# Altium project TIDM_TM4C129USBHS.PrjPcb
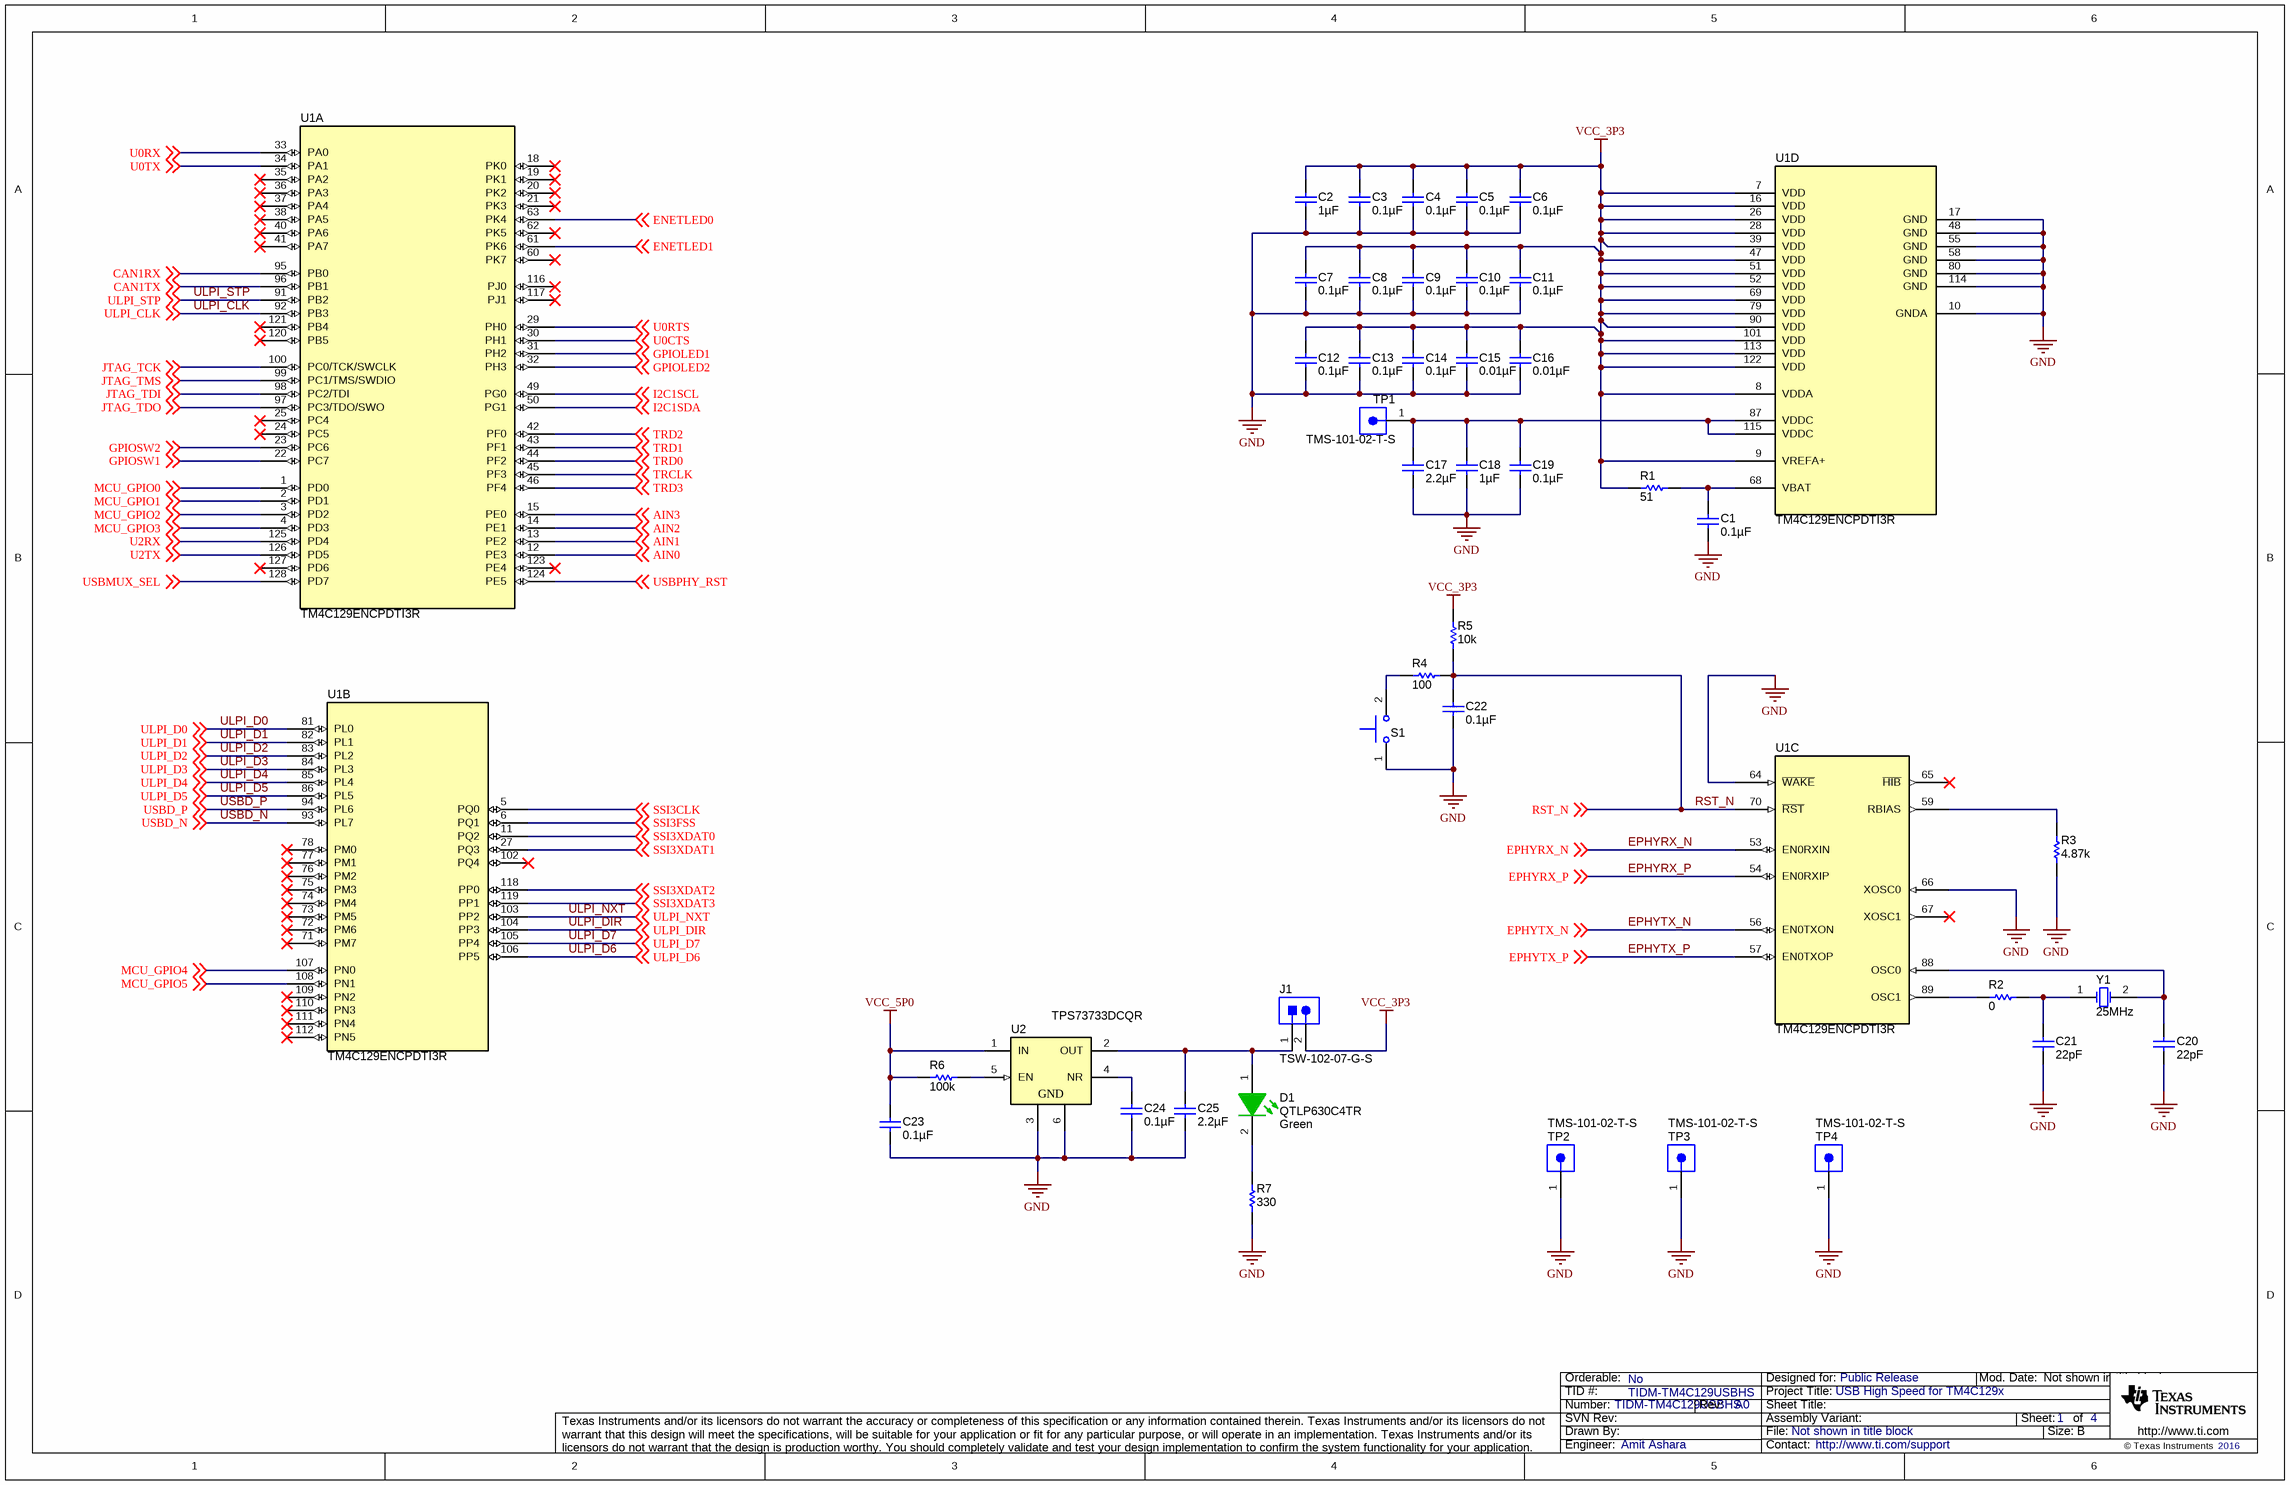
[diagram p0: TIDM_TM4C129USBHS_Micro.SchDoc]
TID: TIDM-TM4C129USBHS; TechSupport: http://www.ti.com/support; SCH_Rev: A0; PRJ_Title: USB High Speed for TM4C129x; PRJ_Number: TIDM-TM4C129USBHS; PRJ_Engineer: Amit Ashara; PRJ_Customer: Public Release; PCB_Rev: A0; PCB_Layout: Amit Ashara; EVM_Orderable: No; CopyrightYear: 2016
4 sheets, 137 parts. Net scope: global (net labels, ports and power ports of the same name join across sheets).
Board file: TIDM_TM4C129USBHS.PcbDoc
Sheets:
  TIDM_TM4C129USBHS_Micro.SchDoc
  TIDM_TM4C129USBHS_Connector.SchDoc
  TIDM_TM4C129USBHS_Ethernet.SchDoc
  TIDM_TM4C129USBHS_USB.SchDoc

## Sheet TIDM_TM4C129USBHS_Micro.SchDoc
size 431 x 279 mm; Date: Not shown in title block; ApprovedBy: Not shown in title block; CheckedBy: Not shown in title block; Author: Not shown in title block; CompanyName: Not shown in title block; Engineer: Not shown in title block; Organization: Not shown in title block; Address1: Not shown in title block; Address2: Not shown in title block; Address3: Not shown in title block; Address4: Not shown in title block; DocumentNumber: 1; Revision: Use project parameter SCH_Rev; SheetNumber: 1; SheetTotal: 4; PageSetup: Record=PageOptions¦CenterHorizontal=True¦CenterVertical=True¦PrintScale=1.00¦XCorrection=1.00¦YCorrection=1.00¦PrintKind=0¦BorderSize=5000000¦LeftOffset=0¦BottomOffset=0¦Orientation=2¦PaperLength=1000¦PaperWidth=1000¦Scale=100¦PaperSource=15¦PrintQuality=600¦MediaType=1¦DitherType=10¦PaperKind=Letter¦PrintScaleMode=1

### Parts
C1  ValueDisplayed: 0.1µF  [0402]  (hidden comment: GRM155R71C104KA88D)
C2  ValueDisplayed: 1µF  [0402]  (hidden comment: C1005X5R1C105K050BC)
C3  ValueDisplayed: 0.1µF  [0402]  (hidden comment: GRM155R71C104KA88D)
C4  ValueDisplayed: 0.1µF  [0402]  (hidden comment: GRM155R71C104KA88D)
C5  ValueDisplayed: 0.1µF  [0402]  (hidden comment: GRM155R71C104KA88D)
C6  ValueDisplayed: 0.1µF  [0402]  (hidden comment: GRM155R71C104KA88D)
C7  ValueDisplayed: 0.1µF  [0402]  (hidden comment: GRM155R71C104KA88D)
C8  ValueDisplayed: 0.1µF  [0402]  (hidden comment: GRM155R71C104KA88D)
C9  ValueDisplayed: 0.1µF  [0402]  (hidden comment: GRM155R71C104KA88D)
C10  ValueDisplayed: 0.1µF  [0402]  (hidden comment: GRM155R71C104KA88D)
C11  ValueDisplayed: 0.1µF  [0402]  (hidden comment: GRM155R71C104KA88D)
C12  ValueDisplayed: 0.1µF  [0402]  (hidden comment: GRM155R71C104KA88D)
C13  ValueDisplayed: 0.1µF  [0402]  (hidden comment: GRM155R71C104KA88D)
C14  ValueDisplayed: 0.1µF  [0402]  (hidden comment: GRM155R71C104KA88D)
C15  ValueDisplayed: 0.01µF  [0402]  (hidden comment: GRM155R71C103KA01D)
C16  ValueDisplayed: 0.01µF  [0402]  (hidden comment: GRM155R71C103KA01D)
C17  ValueDisplayed: 2.2µF  [0402]  (hidden comment: GRM155R61C225KE11D)
C18  ValueDisplayed: 1µF  [0402]  (hidden comment: C1005X5R1C105K050BC)
C19  ValueDisplayed: 0.1µF  [0402]  (hidden comment: GRM155R71C104KA88D)
C20  ValueDisplayed: 22pF  [0402]  (hidden comment: C1005C0G1H220J050BA)
C21  ValueDisplayed: 22pF  [0402]  (hidden comment: C1005C0G1H220J050BA)
C22  ValueDisplayed: 0.1µF  [0603]  (hidden comment: C0603C104J3RAC)
C23  ValueDisplayed: 0.1µF  [0603]  (hidden comment: EMK107B7104KA-T)
C24  ValueDisplayed: 0.1µF  [0603]  (hidden comment: EMK107B7104KA-T)
C25  ValueDisplayed: 2.2µF  [0603]  (hidden comment: GRM188R61C225KE15D)
D1  QTLP630C4TR  value Green  [QTLP630C_Green]
J1  TSW-102-07-G-S  [TSW-102-07-G-S]
R1  ValueDisplayed: 51  [0603]  (hidden comment: CRCW060351R0JNEA)
R2  ValueDisplayed: 0  [0402]  (hidden comment: ERJ-2GE0R00X)
R3  ValueDisplayed: 4.87k  [0402]  (hidden comment: CRCW04024K87FKED)
R4  ValueDisplayed: 100  [0402]  (hidden comment: CRCW0402100RJNED)
R5  ValueDisplayed: 10k  [0402]  (hidden comment: CRCW040210K0JNED)
R6  ValueDisplayed: 100k  [0402]  (hidden comment: ERJ-2RKF1003X)
R7  ValueDisplayed: 330  [0603]  (hidden comment: RC0603JR-07330RL)
S1  SKRKAEE010  [SW_SKRKAEE010]  (value not drawn)
TP1  TMS-101-02-T-S  [SAMTEC_TMS-101-02-T-S]
TP2  TMS-101-02-T-S  [SAMTEC_TMS-101-02-T-S]
TP3  TMS-101-02-T-S  [SAMTEC_TMS-101-02-T-S]
TP4  TMS-101-02-T-S  [SAMTEC_TMS-101-02-T-S]
U1  TM4C129ENCPDTI3R  [PDT0128A_N]  (parts A,B,C,D of 4)
U2  TPS73733DCQR  [DCQ0006A_N]
Y1  Frequency: 25MHz  [NDK_NX5032GA]  (hidden comment: NX5032GA-25.000M-STD-CSK-4)

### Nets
GND: C1.2 C2.2 C3.2 C4.2 C5.2 C6.2 C7.2 C8.2 C9.2 C10.2 C11.2 C12.2 C13.2 C14.2 C15.2 C16.2 C17.2 C18.2 C19.2 C20.2 C21.2 C22.2 C23.2 C24.2 C25.2 R3.1 R7.2 S1.1 TP2.1 TP3.1 TP4.1 U1.10(GNDA) U1.17(GND) U1.48(GND) U1.55(GND) U1.58(GND) U1.64(~{WAKE}) U1.66(XOSC0) U1.80(GND) U1.114(GND) U2.3(GND) U2.6(GND)
VCC_3P3: C2.1 C3.1 C4.1 C5.1 C6.1 C7.1 C8.1 C9.1 C10.1 C11.1 C12.1 C13.1 C14.1 C15.1 C16.1 J1.2 R1.1 R5.2 U1.7(VDD) U1.8(VDDA) U1.9(VREFA+) U1.16(VDD) U1.26(VDD) U1.28(VDD) U1.39(VDD) U1.47(VDD) U1.51(VDD) U1.52(VDD) U1.69(VDD) U1.79(VDD) U1.90(VDD) U1.101(VDD) U1.113(VDD) U1.122(VDD)
VCC_5P0: C23.1 R6.1 U2.1(IN)
AIN0: U1.12(PE3) ; off-sheet AIN0
AIN1: U1.13(PE2) ; off-sheet AIN1
AIN2: U1.14(PE1) ; off-sheet AIN2
AIN3: U1.15(PE0) ; off-sheet AIN3
CAN1RX: U1.95(PB0) ; off-sheet CAN1RX
CAN1TX: U1.96(PB1) ; off-sheet CAN1TX
ENETLED0: U1.63(PK4) ; off-sheet ENETLED0
ENETLED1: U1.61(PK6) ; off-sheet ENETLED1
EPHYRX_N: U1.53(EN0RXIN) ; off-sheet EPHYRX_N
EPHYRX_P: U1.54(EN0RXIP) ; off-sheet EPHYRX_P
EPHYTX_N: U1.56(EN0TXON) ; off-sheet EPHYTX_N
EPHYTX_P: U1.57(EN0TXOP) ; off-sheet EPHYTX_P
GPIOLED1: U1.31(PH2) ; off-sheet GPIOLED1
GPIOLED2: U1.32(PH3) ; off-sheet GPIOLED2
GPIOSW1: U1.22(PC7) ; off-sheet GPIOSW1
GPIOSW2: U1.23(PC6) ; off-sheet GPIOSW2
I2C1SCL: U1.49(PG0) ; off-sheet I2C1SCL
I2C1SDA: U1.50(PG1) ; off-sheet I2C1SDA
JTAG_TCK: U1.100(PC0/TCK/SWCLK) ; off-sheet JTAG_TCK
JTAG_TDI: U1.98(PC2/TDI) ; off-sheet JTAG_TDI
JTAG_TDO: U1.97(PC3/TDO/SWO) ; off-sheet JTAG_TDO
JTAG_TMS: U1.99(PC1/TMS/SWDIO) ; off-sheet JTAG_TMS
MCU_GPIO0: U1.1(PD0) ; off-sheet MCU_GPIO0
MCU_GPIO1: U1.2(PD1) ; off-sheet MCU_GPIO1
MCU_GPIO2: U1.3(PD2) ; off-sheet MCU_GPIO2
MCU_GPIO3: U1.4(PD3) ; off-sheet MCU_GPIO3
MCU_GPIO4: U1.107(PN0) ; off-sheet MCU_GPIO4
MCU_GPIO5: U1.108(PN1) ; off-sheet MCU_GPIO5
RST_N: C22.1 R4.1 R5.1 U1.70(~{RST}) ; off-sheet RST_N
SSI3CLK: U1.5(PQ0) ; off-sheet SSI3CLK
SSI3FSS: U1.6(PQ1) ; off-sheet SSI3FSS
SSI3XDAT0: U1.11(PQ2) ; off-sheet SSI3XDAT0
SSI3XDAT1: U1.27(PQ3) ; off-sheet SSI3XDAT1
SSI3XDAT2: U1.118(PP0) ; off-sheet SSI3XDAT2
SSI3XDAT3: U1.119(PP1) ; off-sheet SSI3XDAT3
TRCLK: U1.45(PF3) ; off-sheet TRCLK
TRD0: U1.44(PF2) ; off-sheet TRD0
TRD1: U1.43(PF1) ; off-sheet TRD1
TRD2: U1.42(PF0) ; off-sheet TRD2
TRD3: U1.46(PF4) ; off-sheet TRD3
U0CTS: U1.30(PH1) ; off-sheet U0CTS
U0RTS: U1.29(PH0) ; off-sheet U0RTS
U0RX: U1.33(PA0) ; off-sheet U0RX
U0TX: U1.34(PA1) ; off-sheet U0TX
U2RX: U1.125(PD4) ; off-sheet U2RX
U2TX: U1.126(PD5) ; off-sheet U2TX
ULPI_CLK: U1.92(PB3) ; off-sheet ULPI_CLK
ULPI_D0: U1.81(PL0) ; off-sheet ULPI_D0
ULPI_D1: U1.82(PL1) ; off-sheet ULPI_D1
ULPI_D2: U1.83(PL2) ; off-sheet ULPI_D2
ULPI_D3: U1.84(PL3) ; off-sheet ULPI_D3
ULPI_D4: U1.85(PL4) ; off-sheet ULPI_D4
ULPI_D5: U1.86(PL5) ; off-sheet ULPI_D5
ULPI_D6: U1.106(PP5) ; off-sheet ULPI_D6
ULPI_D7: U1.105(PP4) ; off-sheet ULPI_D7
ULPI_DIR: U1.104(PP3) ; off-sheet ULPI_DIR
ULPI_NXT: U1.103(PP2) ; off-sheet ULPI_NXT
ULPI_STP: U1.91(PB2) ; off-sheet ULPI_STP
USBD_N: U1.93(PL7) ; off-sheet USBD_N
USBD_P: U1.94(PL6) ; off-sheet USBD_P
USBMUX_SEL: U1.128(PD7) ; off-sheet USBMUX_SEL
USBPHY_RST: U1.124(PE5) ; off-sheet USBPHY_RST
NetC1_1: C1.1 R1.2 U1.68(VBAT)
NetC17_1: C17.1 C18.1 C19.1 TP1.1 U1.87(VDDC) U1.115(VDDC)
NetC20_1: C20.1 U1.88(OSC0) Y1.2(OSC2)
NetC21_1: C21.1 R2.2 Y1.1(OSC1)
NetC24_1: C24.1 U2.4(NR)
NetC25_1: C25.1 D1.1(A) J1.1 U2.2(OUT)
NetD1_2: D1.2(K) R7.1
NetR2_1: R2.1 U1.89(OSC1)
NetR3_2: R3.2 U1.59(RBIAS)
NetR4_2: R4.2 S1.2
NetR6_2: R6.2 U2.5(EN)

Not connected (* = marked no-connect by the designer): U1 18(PK0)* 19(PK1)* 20(PK2)* 21(PK3)* 24(PC5)* 25(PC4)* 35(PA2)* 36(PA3)* 37(PA4)* 38(PA5)* 40(PA6)* 41(PA7)* 60(PK7)* 62(PK5)* 65(~{HIB})* 67(XOSC1)* 71(PM7)* 72(PM6)* 73(PM5)* 74(PM4)* 75(PM3)* 76(PM2)* 77(PM1)* 78(PM0)* 102(PQ4)* 109(PN2)* 110(PN3)* 111(PN4)* 112(PN5)* 116(PJ0)* 117(PJ1)* 120(PB5)* 121(PB4)* 123(PE4)* 127(PD6)*

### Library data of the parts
C1 C3-C14 C19 = GRM155R71C104KA88D: CAP, CERM, 0.1 µF, 16 V, +/- 10%, X7R, 0402; Manufacturer: MuRata; Polarized: N; CompType: Capacitor; Value: 0.1uF; U/M: EA; Cap_F: 0.0000001; Tolerance_%: 10; Value1: Unknown; VDC_V: 16; Value2: 16V; TaMin_C: -55; TaMax_C: 125; AEC Category: Q200
C2 C18 = C1005X5R1C105K050BC: CAP, CERM, 1 µF, 16 V, +/- 10%, X5R, 0402; Manufacturer: TDK; Polarized: N; CompType: Capacitor; Value: 1uF; U/M: EA; Cap_F: 0.000001; Tolerance_%: 10; Value1: Unknown; VDC_V: 16; Value2: 16V; TaMin_C: -55; TaMax_C: 85; AEC Category: Q200
C15 C16 = GRM155R71C103KA01D: CAP, CERM, 0.01 µF, 16 V, +/- 10%, X7R, 0402; Manufacturer: MuRata; Polarized: N; CompType: Capacitor; Value: 0.01uF; U/M: EA; Cap_F: 0.00000001; Tolerance_%: 10; Value1: Unknown; VDC_V: 16; Value2: 16V; TaMin_C: -55; TaMax_C: 125; AEC Category: Q200
C17 = GRM155R61C225KE11D: CAP, CERM, 2.2 µF, 16 V, +/- 10%, X5R, 0402; Manufacturer: MuRata; Polarized: N; CompType: Capacitor; Value: 2.2uF; U/M: EA; Cap_F: 0.0000022; Tolerance_%: 10; Value1: Unknown; VDC_V: 16; Value2: 16V; TaMin_C: -55; TaMax_C: 85; AEC Category: Q200
C20 C21 = C1005C0G1H220J050BA: CAP, CERM, 22 pF, 50 V, +/- 5%, C0G/NP0, 0402; Manufacturer: TDK; Polarized: N; CompType: Capacitor; Value: 22pF; U/M: EA; Cap_F: 0.000000000022; Tolerance_%: 5; Value1: Unknown; VDC_V: 50; Value2: 50V; TaMin_C: -55; TaMax_C: 125; AEC Category: Q200
C22 = C0603C104J3RAC: CAP, CERM, 0.1 µF, 25 V, +/- 5%, X7R, 0603; Manufacturer: Kemet; Polarized: N; CompType: Capacitor; Value: 0.1uF; U/M: EA; Cap_F: 0.0000001; Tolerance_%: 5; Value1: Unknown; VDC_V: 25; Value2: 25V; TaMin_C: -55; TaMax_C: 125; AEC Category: Q200
C23 C24 = EMK107B7104KA-T: CAP, CERM, 0.1 µF, 16 V, +/- 10%, X7R, 0603; Manufacturer: Taiyo Yuden; Polarized: N; CompType: Capacitor; Value: 0.1uF; U/M: EA; Cap_F: 0.0000001; Tolerance_%: 10; Value1: Unknown; VDC_V: 16; Value2: 16V; TaMin_C: -55; TaMax_C: 125; AEC Category: Q200
C25 = GRM188R61C225KE15D: CAP, CERM, 2.2 µF, 16 V, +/- 10%, X5R, 0603; Manufacturer: MuRata; Polarized: N; CompType: Capacitor; Value: 2.2uF; U/M: EA; Cap_F: 0.0000022; Tolerance_%: 10; Value1: Unknown; VDC_V: 16; Value2: 16V; TaMin_C: -55; TaMax_C: 85; AEC Category: Q200
D1 = QTLP630C4TR: LED, Green, SMD; Manufacturer: Everlight; SymbolCreator: Altium; Vf_V: 2.1; Value2: 2.1V; Io_A: 0.02; Vr_V: 5; Tjmax_C: 85; Value1: W; Angle: 140; U/M: EA
J1 = TSW-102-07-G-S: Header, 100mil, 2x1, Gold, TH; Manufacturer: Samtec; SymbolCreator: a0412235; Pitch_mm: 2.54; Gender: Male; Shrouded: N; Row_Count: 1; Current_A: 6.3; Voltage_V: 550; Cert_CSA: Y
R1 = CRCW060351R0JNEA: RES, 51, 5%, 0.1 W, 0603; Manufacturer: Vishay-Dale; CompType: Resistor; Value: 51; Value_Code: 51R0; Tolerance_%: 5; Power_W: 0.1; Value2: 0.1W; VDC_V: 75; TempCo: 200 ppm/C; EIA_Code: E24; U/M: EA; AEC Category: Q200
R2 = ERJ-2GE0R00X: RES, 0, 5%, 0.063 W, 0402; Manufacturer: Panasonic; CompType: Resistor; Value: 0; Value_Code: 0000; Tolerance_%: 5; Power_W: 0.063; Value2: 0.063W; VDC_V: 50; TempCo: 600 ppm/C; EIA_Code: E24; U/M: EA; AEC Category: Q200
R3 = CRCW04024K87FKED: RES, 4.87 k, 1%, 0.063 W, 0402; Manufacturer: Vishay-Dale; CompType: Resistor; Value: 4.87k; Res_ohm: 4870; Value_Code: 4k87; Tolerance_%: 1; Power_W: 0.063; Value2: 0.063W; VDC_V: 50; TempCo: 100 ppm/C; EIA_Code: E96; U/M: EA; AEC Category: Q200
R4 = CRCW0402100RJNED: RES, 100, 5%, 0.063 W, 0402; Manufacturer: Vishay-Dale; CompType: Resistor; Value: 100; Value_Code: 100R; Tolerance_%: 5; Power_W: 0.063; Value2: 0.063W; VDC_V: 50; TempCo: 200 ppm/C; EIA_Code: E24; U/M: EA; AEC Category: Q200
R5 = CRCW040210K0JNED: RES, 10 k, 5%, 0.063 W, 0402; Manufacturer: Vishay-Dale; CompType: Resistor; Value: 10k; Res_ohm: 10000; Value_Code: 10k0; Tolerance_%: 5; Power_W: 0.063; Value2: 0.063W; VDC_V: 50; TempCo: 200 ppm/C; EIA_Code: E24; U/M: EA; AEC Category: Q200
R6 = ERJ-2RKF1003X: RES, 100 k, 1%, 0.1 W, 0402; Manufacturer: Panasonic; CompType: Resistor; Value: 100k; Res_ohm: 100000; Tolerance_%: 1; Power_W: 0.1; Value2: 0.1W; VDC_V: 50; TempCo: 100 ppm/C; EIA_Code: E96; U/M: EA; AEC Category: Q200
R7 = RC0603JR-07330RL: RES, 330, 5%, 0.1 W, 0603; Manufacturer: Yageo America; CompType: Resistor; Value: 330; Value_Code: 330R; Tolerance_%: 5; Power_W: 0.1; Value2: 0.1W; VDC_V: 50; TempCo: 100 ppm/C; EIA_Code: E24; U/M: EA; AEC Category: Q200
S1 = SKRKAEE010: Switch, Push Button, SMD; Manufacturer: Alps; SymbolCreator: a0412235; Circuit: SPST-NO; VDC_V: 12; SwitchFunction: Off-Mom; PositionCount: 1; CurrentRating_mA: 50
TP1-TP4 = TMS-101-02-T-S: Header, 1x1, Tin, TH; Manufacturer: Samtec; SymbolCreator: a0412235
U1 = TM4C129ENCPDTI3R: Tiva C Series Microcontroller, PDT0128A; Manufacturer: Texas Instruments; SymbolCreator: a0411947; CompType: IC; U/M: EA
U2 = TPS73733DCQR: Single Output LDO, 1 A, Fixed 3.3 V Output, 2.2 to 5.5 V Input, with Reverse Current Protection, 6-pin SOT-223 (DCQ), -40 to 125 degC, Green (RoHS & no Sb/Br); Manufacturer: Texas Instruments; Alternate PartNumber: Equivalent; Accuracy(%): 3; Fixed Output Options(V): 3.3; Iout(Max)(A): 1; Iq(Typ)(mA): 0.3; Rating: Catalog; SubFamily: Single Channel LDO; Vdo(Typ)(mV): 130; Vin(Max)(V): 5.5; Vin(Min)(V): 2.2
Y1 = NX5032GA-25.000M-STD-CSK-4: Crystal, 25MHz,  SMD; Manufacturer: NDK; SymbolCreator: a0412235; U/M: EA; TaMin_C: -40; TaMax_C: 150; Frequency Stability: ±30ppm

## Sheet TIDM_TM4C129USBHS_Connector.SchDoc
size 431 x 279 mm; Date: Not shown in title block; ApprovedBy: Not shown in title block; CheckedBy: Not shown in title block; Author: Not shown in title block; CompanyName: Not shown in title block; Engineer: Not shown in title block; Organization: Not shown in title block; Address1: Not shown in title block; Address2: Not shown in title block; Address3: Not shown in title block; Address4: Not shown in title block; DocumentNumber: 1; Revision: Use project parameter SCH_Rev; SheetNumber: 2; SheetTotal: 4; PageSetup: Record=PageOptions¦CenterHorizontal=True¦CenterVertical=True¦PrintScale=1.00¦XCorrection=1.00¦YCorrection=1.00¦PrintKind=0¦BorderSize=5000000¦LeftOffset=0¦BottomOffset=0¦Orientation=2¦PaperLength=1000¦PaperWidth=1000¦Scale=100¦PaperSource=15¦PrintQuality=600¦MediaType=1¦DitherType=10¦PaperKind=Letter¦PrintScaleMode=1
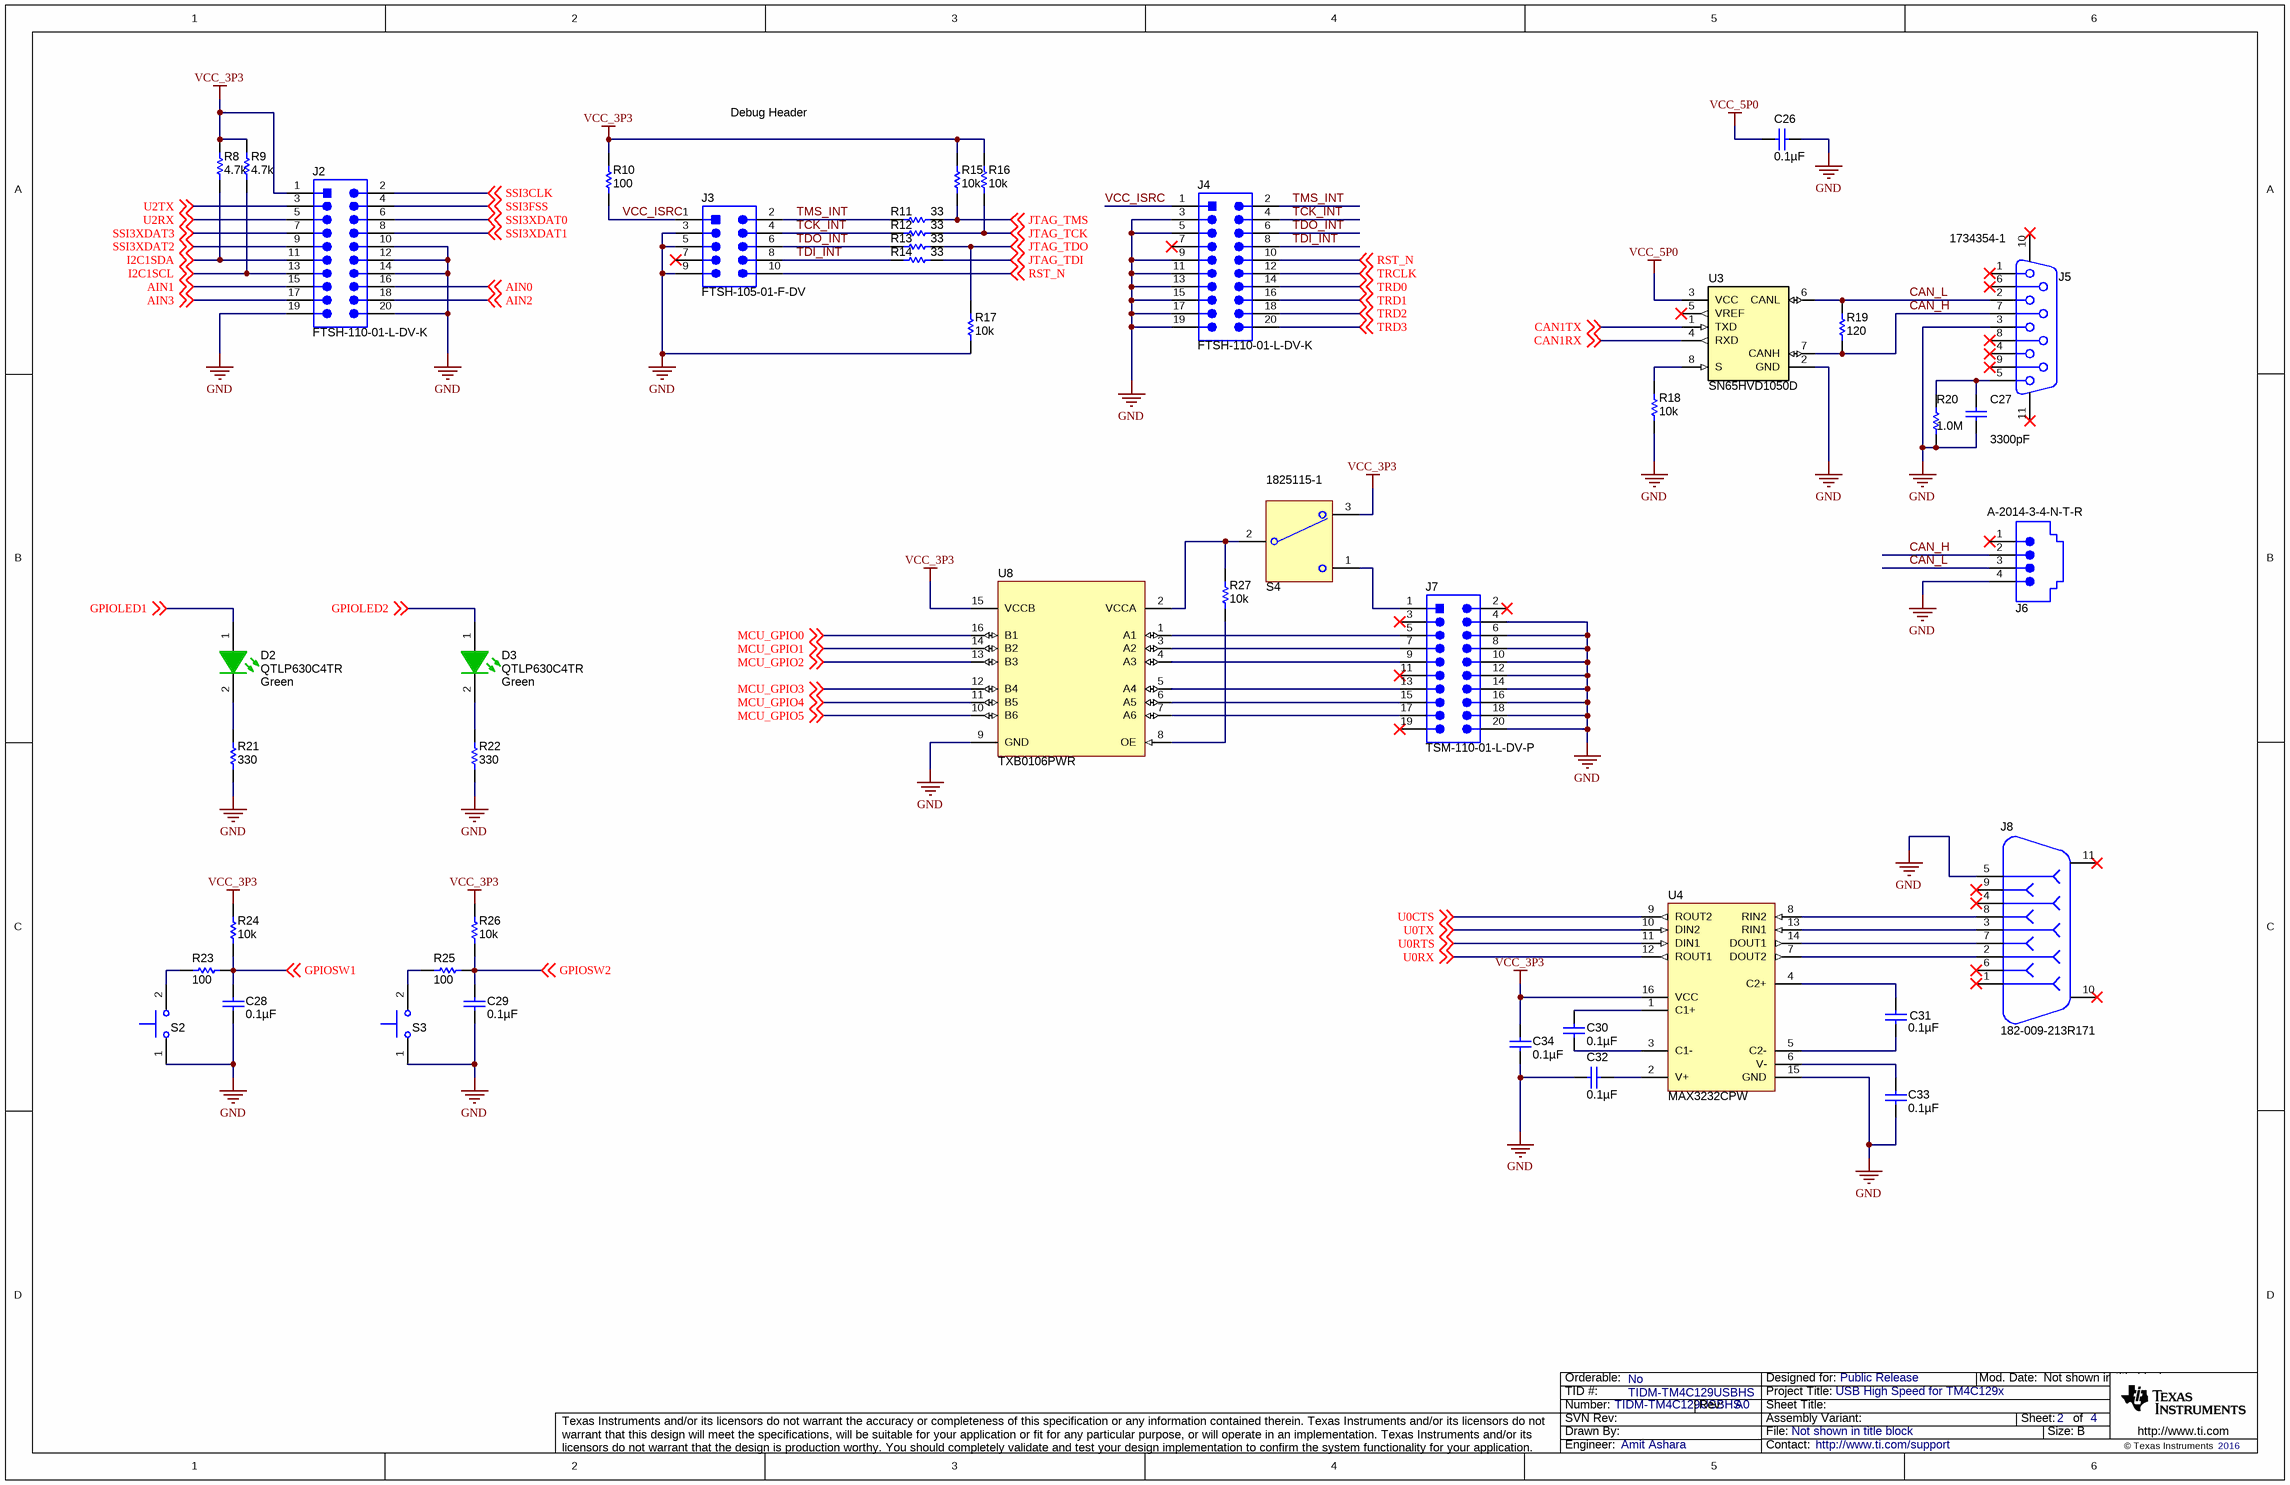
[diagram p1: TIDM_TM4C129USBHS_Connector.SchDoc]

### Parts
C26  ValueDisplayed: 0.1µF  [0402]  (hidden comment: GRM155R71C104KA88D)
C27  ValueDisplayed: 3300pF  [0603]  (hidden comment: C0603X332K5RACTU)
C28  ValueDisplayed: 0.1µF  [0603]  (hidden comment: C0603C104J3RAC)
C29  ValueDisplayed: 0.1µF  [0603]  (hidden comment: C0603C104J3RAC)
C30  ValueDisplayed: 0.1µF  [0402]  (hidden comment: C1005X5R0J104K)
C31  ValueDisplayed: 0.1µF  [0402]  (hidden comment: C1005X5R0J104K)
C32  ValueDisplayed: 0.1µF  [0805_HV]  (hidden comment: 08053C104KAT2A)
C33  ValueDisplayed: 0.1µF  [0402]  (hidden comment: C1005X5R0J104K)
C34  ValueDisplayed: 0.1µF  [0402]  (hidden comment: C1005X5R0J104K)
D2  QTLP630C4TR  value Green  [QTLP630C_Green]
D3  QTLP630C4TR  value Green  [QTLP630C_Green]
J2  FTSH-110-01-L-DV-K  [Samtec_FTSH-110-01-x-DV-K]
J3  FTSH-105-01-F-DV  [Samtec_FTSH-105-01-x-DV]
J4  FTSH-110-01-L-DV-K  [Samtec_FTSH-110-01-x-DV-K]
J5  1734354-1  [TE_1734354-1]
J6  A-2014-3-4-N-T-R  [Assman_A-2014-3-x-N-T-R]
J7  TSM-110-01-L-DV-P  [CONN_TSM-110-01-T-DV-P]
J8  182-009-213R171  [NORCOMP_182-009-213R171]
R8  ValueDisplayed: 4.7k  [0603]  (hidden comment: CRCW06034K70JNEA)
R9  ValueDisplayed: 4.7k  [0603]  (hidden comment: CRCW06034K70JNEA)
R10  ValueDisplayed: 100  [0603]  (hidden comment: CRCW0603100RJNEA)
R11  ValueDisplayed: 33  [0603]  (hidden comment: CRCW060333R0JNEA)
R12  ValueDisplayed: 33  [0603]  (hidden comment: CRCW060333R0JNEA)
R13  ValueDisplayed: 33  [0603]  (hidden comment: CRCW060333R0JNEA)
R14  ValueDisplayed: 33  [0603]  (hidden comment: CRCW060333R0JNEA)
R15  ValueDisplayed: 10k  [0603]  (hidden comment: CRCW060310K0JNEA)
R16  ValueDisplayed: 10k  [0603]  (hidden comment: CRCW060310K0JNEA)
R17  ValueDisplayed: 10k  [0603]  (hidden comment: CRCW060310K0JNEA)
R18  ValueDisplayed: 10k  [0603]  (hidden comment: CRCW060310K0JNEA)
R19  ValueDisplayed: 120  [0603]  (hidden comment: RC0603FR-07120RL)
R20  ValueDisplayed: 1.0M  [0603]  (hidden comment: CRCW06031M00JNEA)
R21  ValueDisplayed: 330  [0603]  (hidden comment: RC0603JR-07330RL)
R22  ValueDisplayed: 330  [0603]  (hidden comment: RC0603JR-07330RL)
R23  ValueDisplayed: 100  [0402]  (hidden comment: CRCW0402100RJNED)
R24  ValueDisplayed: 10k  [0402]  (hidden comment: CRCW040210K0JNED)
R25  ValueDisplayed: 100  [0402]  (hidden comment: CRCW0402100RJNED)
R26  ValueDisplayed: 10k  [0402]  (hidden comment: CRCW040210K0JNED)
R27  ValueDisplayed: 10k  [0603]  (hidden comment: CRCW060310K0JNEA)
S2  SKRKAEE010  [SW_SKRKAEE010]  (value not drawn)
S3  SKRKAEE010  [SW_SKRKAEE010]  (value not drawn)
S4  1825115-1  [SW_1825115-1]
U3  SN65HVD1050D  [D0008A_L]
U4  MAX3232CPW  [PW0016A_N]
U8  TXB0106PWR  [PW0016A_N]

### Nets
GND: C26.2 C27.2 C28.2 C29.2 C32.1 C33.2 C34.2 J2.10 J2.12 J2.14 J2.19 J2.20 J3.3 J3.5 J3.9 J4.3 J4.5 J4.9 J4.11 J4.13 J4.15 J4.17 J4.19 J5.3 J6.4 J7.4 J7.6 J7.8 J7.10 J7.12 J7.14 J7.16 J7.18 J7.20 J8.5 R17.1 R18.1 R20.1 R21.2 R22.2 S2.1 S3.1 U3.2(GND) U4.15(GND) U8.9(GND)
VCC_3P3: C34.1 J2.1 R8.2 R9.2 R10.1 R15.2 R16.2 R24.2 R26.2 S4.3 U4.16(VCC) U8.15(VCCB)
VCC_5P0: C26.1 U3.3(VCC)
AIN0: J2.16 ; off-sheet AIN0
AIN1: J2.15 ; off-sheet AIN1
AIN2: J2.18 ; off-sheet AIN2
AIN3: J2.17 ; off-sheet AIN3
CAN1RX: U3.4(RXD) ; off-sheet CAN1RX
CAN1TX: U3.1(TXD) ; off-sheet CAN1TX
CAN_H: J5.7 J6.2 R19.1 U3.7(CANH)
CAN_L: J5.2 J6.3 R19.2 U3.6(CANL)
GPIOLED1: D2.1(A) ; off-sheet GPIOLED1
GPIOLED2: D3.1(A) ; off-sheet GPIOLED2
GPIOSW1: C28.1 R23.1 R24.1 ; off-sheet GPIOSW1
GPIOSW2: C29.1 R25.1 R26.1 ; off-sheet GPIOSW2
I2C1SCL: J2.13 R9.1 ; off-sheet I2C1SCL
I2C1SDA: J2.11 R8.1 ; off-sheet I2C1SDA
JTAG_TCK: R12.2 R16.1 ; off-sheet JTAG_TCK
JTAG_TDI: R14.2 ; off-sheet JTAG_TDI
JTAG_TDO: R13.2 R17.2 ; off-sheet JTAG_TDO
JTAG_TMS: R11.2 R15.1 ; off-sheet JTAG_TMS
MCU_GPIO0: U8.16(B1) ; off-sheet MCU_GPIO0
MCU_GPIO1: U8.14(B2) ; off-sheet MCU_GPIO1
MCU_GPIO2: U8.13(B3) ; off-sheet MCU_GPIO2
MCU_GPIO3: U8.12(B4) ; off-sheet MCU_GPIO3
MCU_GPIO4: U8.11(B5) ; off-sheet MCU_GPIO4
MCU_GPIO5: U8.10(B6) ; off-sheet MCU_GPIO5
RST_N: J3.10 J4.10 ; off-sheet RST_N
SSI3CLK: J2.2 ; off-sheet SSI3CLK
SSI3FSS: J2.4 ; off-sheet SSI3FSS
SSI3XDAT0: J2.6 ; off-sheet SSI3XDAT0
SSI3XDAT1: J2.8 ; off-sheet SSI3XDAT1
SSI3XDAT2: J2.9 ; off-sheet SSI3XDAT2
SSI3XDAT3: J2.7 ; off-sheet SSI3XDAT3
TCK_INT: J3.4 J4.4 R12.1
TDI_INT: J3.8 J4.8 R14.1
TDO_INT: J3.6 J4.6 R13.1
TMS_INT: J3.2 J4.2 R11.1
TRCLK: J4.12 ; off-sheet TRCLK
TRD0: J4.14 ; off-sheet TRD0
TRD1: J4.16 ; off-sheet TRD1
TRD2: J4.18 ; off-sheet TRD2
TRD3: J4.20 ; off-sheet TRD3
U0CTS: U4.9(ROUT2) ; off-sheet U0CTS
U0RTS: U4.11(DIN1) ; off-sheet U0RTS
U0RX: U4.12(ROUT1) ; off-sheet U0RX
U0TX: U4.10(DIN2) ; off-sheet U0TX
U2RX: J2.5 ; off-sheet U2RX
U2TX: J2.3 ; off-sheet U2TX
VCC_ISRC: J3.1 J4.1 R10.2
NetC27_1: C27.1 J5.5 R20.2
NetC30_1: C30.1 U4.1(C1+)
NetC30_2: C30.2 U4.3(C1-)
NetC31_1: C31.1 U4.4(C2+)
NetC31_2: C31.2 U4.5(C2-)
NetC32_2: C32.2 U4.2(V+)
NetC33_1: C33.1 U4.6(V-)
NetD2_2: D2.2(K) R21.1
NetD3_2: D3.2(K) R22.1
NetJ7_1: J7.1 S4.1
NetJ7_5: J7.5 U8.1(A1)
NetJ7_7: J7.7 U8.3(A2)
NetJ7_9: J7.9 U8.4(A3)
NetJ7_13: J7.13 U8.5(A4)
NetJ7_15: J7.15 U8.6(A5)
NetJ7_17: J7.17 U8.7(A6)
NetJ8_2: J8.2 U4.7(DOUT2)
NetJ8_3: J8.3 U4.13(RIN1)
NetJ8_7: J8.7 U4.14(DOUT1)
NetJ8_8: J8.8 U4.8(RIN2)
NetR18_2: R18.2 U3.8(S)
NetR23_2: R23.2 S2.2
NetR25_2: R25.2 S3.2
NetR27_1: R27.1 U8.8(OE)
NetR27_2: R27.2 S4.2(COM) U8.2(VCCA)

Not connected (* = marked no-connect by the designer): J3 7*; J4 7*; J5 1* 4* 6* 8* 9* 10* 11*; J6 1*; J7 2* 3* 11* 19*; J8 1* 4* 6* 9* 10* 11*; U3 5(VREF)*

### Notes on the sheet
- Debug Header

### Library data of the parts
C26 = GRM155R71C104KA88D: as C1 on sheet TIDM_TM4C129USBHS_Micro
C27 = C0603X332K5RACTU: CAP, CERM, 3300 pF, 50 V, +/- 10%, X7R, 0603; Manufacturer: Kemet; Polarized: N; CompType: Capacitor; Value: 3300pF; U/M: EA; Cap_F: 0.0000000033; Tolerance_%: 10; Value1: Unknown; VDC_V: 50; Value2: 50V; TaMin_C: -55; TaMax_C: 125; AEC Category: Q200
C28 C29 = C0603C104J3RAC: as C22 on sheet TIDM_TM4C129USBHS_Micro
C30 C31 C33 C34 = C1005X5R0J104K: CAP, CERM, 0.1 µF, 6.3 V, +/- 10%, X5R, 0402; Manufacturer: TDK; Polarized: N; CompType: Capacitor; Value: 0.1uF; U/M: EA; Cap_F: 0.0000001; Tolerance_%: 10; ESR_ohm: 0.0186; Value1: 0.0186 ohm; VDC_V: 6.3; Value2: 6.3V; TaMin_C: -55; TaMax_C: 85
C32 = 08053C104KAT2A: CAP, CERM, 0.1 µF, 25 V, +/- 10%, X7R, 0805; Manufacturer: AVX; Polarized: N; CompType: Capacitor; Value: 0.1uF; U/M: EA; Cap_F: 0.0000001; Tolerance_%: 10; ESR_ohm: 0.28; Value1: 0.28 ohm; VDC_V: 25; Value2: 25V; TaMin_C: -55; TaMax_C: 125; Cap_Case: 0805
D2 D3 = QTLP630C4TR: as D1 on sheet TIDM_TM4C129USBHS_Micro
J2 J4 = FTSH-110-01-L-DV-K: Header (Shrouded), 1.27mm, 10x2, Tin, SMT; Manufacturer: Samtec; SymbolCreator: a0412235; Pitch_mm: 1.27; Gender: Male; Shrouded: Y; Row_Count: 2; Current_A: 3.3
J3 = FTSH-105-01-F-DV: Header, 1.27mm, 5x2, Gold, Black, SMT; Manufacturer: Samtec; SymbolCreator: a0412235; Pitch_mm: 1.27; Gender: Male; Row_Count: 2; Current_A: 3.3; Cert_CSA: Y
J5 = 1734354-1: Receptacle, D-Sub, 9 Position, R/A, TH; Manufacturer: TE Connectivity; SymbolCreator: Altium; Gender: Female; ContactFinish: Gold
J6 = A-2014-3-4-N-T-R: Modular Connector, Jack, 4P4C, Gold, TH; Manufacturer: Assman WSW; SymbolCreator: Altium; Pitch_mm: 1.27; Gender: Female; Row_Count: 2; RowSpacing_mm: 2.54; Current_A: 1.5; Voltage_V: 125; Cert_UL: Y
J7 = TSM-110-01-L-DV-P: Header, 2.54mm, 10x2, Gold, SMT; Manufacturer: Samtec; SymbolCreator: a0412235; Pitch_mm: 2.54; Gender: Male; Shrouded: N; Row_Count: 2; Current_A: 5.4; Voltage_V: 475; Cert_CSA: Y
J8 = 182-009-213R171: CONN DB9 FEMALE R/A SOLDER TH; Manufacturer: NorComp; SymbolCreator: a0412235; CompType: Connector; U/M: EA
R8 R9 = CRCW06034K70JNEA: RES, 4.7 k, 5%, 0.1 W, 0603; Manufacturer: Vishay-Dale; CompType: Resistor; Value: 4.7k; Res_ohm: 4700; Value_Code: 4k70; Tolerance_%: 5; Power_W: 0.1; Value2: 0.1W; VDC_V: 75; TempCo: 200 ppm/C; EIA_Code: E24; U/M: EA; AEC Category: Q200
R10 = CRCW0603100RJNEA: RES, 100, 5%, 0.1 W, 0603; Manufacturer: Vishay-Dale; CompType: Resistor; Value: 100; Value_Code: 100R; Tolerance_%: 5; Power_W: 0.1; Value2: 0.1W; VDC_V: 75; TempCo: 200 ppm/C; EIA_Code: E24; U/M: EA; AEC Category: Q200
R11-R14 = CRCW060333R0JNEA: RES, 33, 5%, 0.1 W, 0603; Manufacturer: Vishay-Dale; CompType: Resistor; Value: 33; Value_Code: 33R0; Tolerance_%: 5; Power_W: 0.1; Value2: 0.1W; VDC_V: 75; TempCo: 200 ppm/C; EIA_Code: E24; U/M: EA; AEC Category: Q200
R15-R18 R27 = CRCW060310K0JNEA: RES, 10 k, 5%, 0.1 W, 0603; Manufacturer: Vishay-Dale; CompType: Resistor; Value: 10k; Res_ohm: 10000; Value_Code: 10k0; Tolerance_%: 5; Power_W: 0.1; Value2: 0.1W; VDC_V: 75; TempCo: 200 ppm/C; EIA_Code: E24; U/M: EA; AEC Category: Q200
R19 = RC0603FR-07120RL: RES, 120, 1%, 0.1 W, 0603; Manufacturer: Yageo America; CompType: Resistor; Value: 120; Value_Code: 120R; Tolerance_%: 1; Power_W: 0.1; Value2: 0.1W; VDC_V: 150; TempCo: 200 ppm/C; U/M: EA; AEC Category: Q200
R20 = CRCW06031M00JNEA: RES, 1.0 M, 5%, 0.1 W, 0603; Manufacturer: Vishay-Dale; CompType: Resistor; Value: 1.0Meg; Res_ohm: 1000000; Value_Code: 1M00; Tolerance_%: 5; Power_W: 0.1; Value2: 0.1W; VDC_V: 75; TempCo: 200 ppm/C; EIA_Code: E24; U/M: EA; AEC Category: Q200
R21 R22 = RC0603JR-07330RL: as R7 on sheet TIDM_TM4C129USBHS_Micro
R23 R25 = CRCW0402100RJNED: as R4 on sheet TIDM_TM4C129USBHS_Micro
R24 R26 = CRCW040210K0JNED: as R5 on sheet TIDM_TM4C129USBHS_Micro
S2 S3 = SKRKAEE010: as S1 on sheet TIDM_TM4C129USBHS_Micro
S4 = 1825115-1: Switch, SPDT, On-On, 2 Pos, TH; Manufacturer: TE Connectivity; SymbolCreator: x0208326; VDC_V: 12; PositionCount: 2; CurrentRating_mA: 150
U3 = SN65HVD1050D: High-Speed EMC Optimized CAN Transceiver, 70 mA, 5 V, -40 to 125 degC, 8-pin SOIC (D), Green (RoHS & no Sb/Br); Manufacturer: Texas Instruments; Alternate PartNumber: Equivalent; Drivers Per Package: 1; Bus Fault Voltage(V): -4 to 16; Transient Pulse Protection(V): -200 to 200; ICC(Max)(mA): 70; Supply Voltage(s)(V): 5; Rating: Catalog
U4 = MAX3232CPW: 3-V to 5.5-V Multichannel RS-232 Line Driver / Receiver with ±15-kV ESD Protection, 0 to 70 degC, 16-Pin TSSOP (PW), Green (RoHS & no Sb/Br); Manufacturer: Texas Instruments; Alternate Manufacturer: None; Alternate PartNumber: Equivalent; Drivers Per Package: 2; Supply Voltage(s)(V): 3.3 or 5.0; ESD HBM(kV): +/-15; ICC(Max)(mA): 1; Single Supply: TRUE
U8 = TXB0106PWR: 6-BIT BIDIRECTIONAL VOLTAGE-LEVEL TRANSLATOR WITH AUTO-DIRECTION SENSING AND ±15-kV ESD PROTECTION, PW0016A; Manufacturer: Texas Instruments; SymbolCreator: Altium; CompType: IC; U/M: EA

## Sheet TIDM_TM4C129USBHS_Ethernet.SchDoc
size 431 x 279 mm; Date: Not shown in title block; ApprovedBy: Not shown in title block; CheckedBy: Not shown in title block; Author: Not shown in title block; CompanyName: Not shown in title block; Engineer: Not shown in title block; Organization: Not shown in title block; Address1: Not shown in title block; Address2: Not shown in title block; Address3: Not shown in title block; Address4: Not shown in title block; DocumentNumber: 1; Revision: Use project parameter SCH_Rev; SheetNumber: 3; SheetTotal: 4; PageSetup: Record=PageOptions¦CenterHorizontal=True¦CenterVertical=True¦PrintScale=1.00¦XCorrection=1.00¦YCorrection=1.00¦PrintKind=0¦BorderSize=5000000¦LeftOffset=0¦BottomOffset=0¦Orientation=2¦PaperLength=1000¦PaperWidth=1000¦Scale=100¦PaperSource=15¦PrintQuality=600¦MediaType=1¦DitherType=10¦PaperKind=Letter¦PrintScaleMode=1
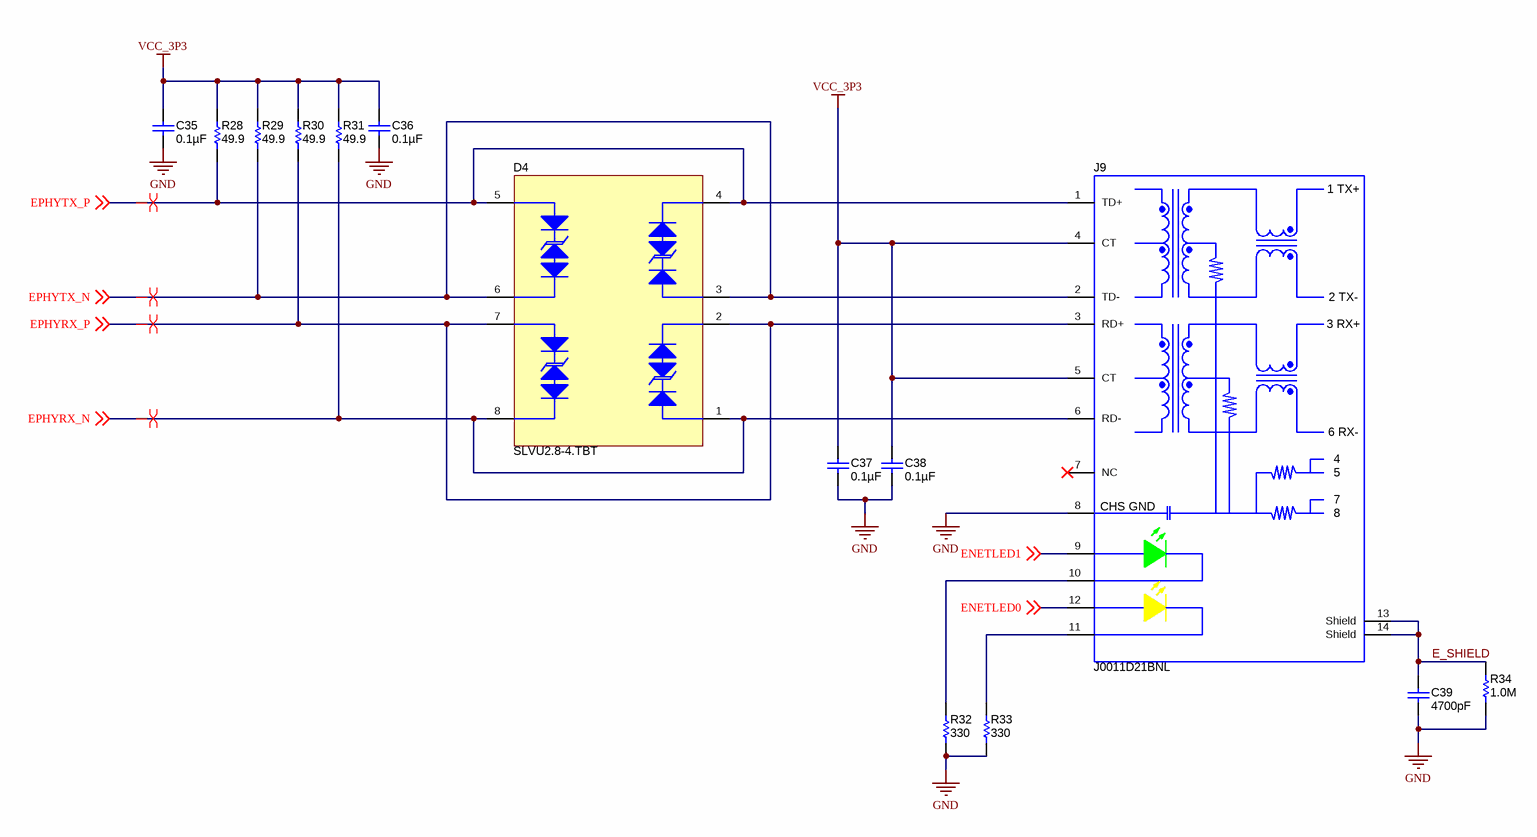
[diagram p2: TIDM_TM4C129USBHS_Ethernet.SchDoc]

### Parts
C35  ValueDisplayed: 0.1µF  [0402]  (hidden comment: GCM155R71C104KA55D)
C36  ValueDisplayed: 0.1µF  [0402]  (hidden comment: GCM155R71C104KA55D)
C37  ValueDisplayed: 0.1µF  [0402]  (hidden comment: GCM155R71C104KA55D)
C38  ValueDisplayed: 0.1µF  [0402]  (hidden comment: GCM155R71C104KA55D)
C39  ValueDisplayed: 4700pF  [1812]  (hidden comment: 1812GC472KA1)
D4  SLVU2.8-4.TBT  [SO-8]
J9  J0011D21BNL  [Pulse_J0011D21BNL]
R28  ValueDisplayed: 49.9  [0402]  (hidden comment: CRCW040249R9FKED)
R29  ValueDisplayed: 49.9  [0402]  (hidden comment: CRCW040249R9FKED)
R30  ValueDisplayed: 49.9  [0402]  (hidden comment: CRCW040249R9FKED)
R31  ValueDisplayed: 49.9  [0402]  (hidden comment: CRCW040249R9FKED)
R32  ValueDisplayed: 330  [0603]  (hidden comment: RC0603JR-07330RL)
R33  ValueDisplayed: 330  [0603]  (hidden comment: RC0603JR-07330RL)
R34  ValueDisplayed: 1.0M  [1206]  (hidden comment: CRCW12061M00JNEA)

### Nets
GND: C35.2 C36.2 C37.2 C38.2 C39.2 J9.8(CHS_GND) R32.2 R33.2 R34.1
VCC_3P3: C35.1 C36.1 C37.1 C38.1 J9.4(CT) J9.5(CT) R28.2 R29.2 R30.2 R31.2
E_SHIELD: C39.1 J9.13(Shield) J9.14(Shield) R34.2
ENETLED0: J9.12(RIGHT_LED) ; off-sheet ENETLED0
ENETLED1: J9.9(LEFT_LED_ANODE) ; off-sheet ENETLED1
EPHYRX_N: D4.1 D4.8 J9.6(RD-) R31.1 ; off-sheet EPHYRX_N
EPHYRX_P: D4.2 D4.7 J9.3(RD+) R30.1 ; off-sheet EPHYRX_P
EPHYTX_N: D4.3 D4.6 J9.2(TD-) R29.1 ; off-sheet EPHYTX_N
EPHYTX_P: D4.4 D4.5 J9.1(TD+) R28.1 ; off-sheet EPHYTX_P
NetJ9_10: J9.10(LEFT_LED) R32.1
NetJ9_11: J9.11(RIGHT_LED_ANODE) R33.1

Not connected (* = marked no-connect by the designer): J9 7(NC)*

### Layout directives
differential pair: EPHYRX_N, EPHYRX_P, EPHYTX_N, EPHYTX_P

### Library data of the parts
C35-C38 = GCM155R71C104KA55D: CAP, CERM, 0.1 µF, 16 V, +/- 10%, X7R, 0402; Manufacturer: MuRata; Polarized: N; CompType: Capacitor; Value: 0.1uF; U/M: EA; Cap_F: 0.0000001; Tolerance_%: 10; Value1: Unknown; VDC_V: 16; Value2: 16V; TaMin_C: -55; TaMax_C: 125; AEC Category: Q200
C39 = 1812GC472KA1: CAP, CERM, 4700 pF, 2000 V, +/- 10%, X7R, 1812; Manufacturer: AVX; Polarized: N; CompType: Capacitor; Value: 4700pF; U/M: EA; Cap_F: 0.0000000047; Tolerance_%: 10; Value1: Unknown; VDC_V: 2000; Value2: 2000V; TaMin_C: -55; TaMax_C: 125; AEC Category: Q200
D4 = SLVU2.8-4.TBT: Diode, TVS, Uni, 2.8 V, 400 W, SO-8; Manufacturer: Semtech; SymbolCreator: Altium; U/M: EA; Power_W: 400; Vr_V: 2.8; Value1: 400W; AEC Category: Q101
J9 = J0011D21BNL: Connector, RJ-45 with integrated magnetics, 1x1, Gold, R/A, TH; Manufacturer: Pulse Engineering; SymbolCreator: Altium
R28-R31 = CRCW040249R9FKED: RES, 49.9, 1%, 0.063 W, 0402; Manufacturer: Vishay-Dale; CompType: Resistor; Value: 49.9; Value_Code: 49R9; Tolerance_%: 1; Power_W: 0.063; Value2: 0.063W; VDC_V: 50; TempCo: 100 ppm/C; EIA_Code: E96; U/M: EA; AEC Category: Q200
R32 R33 = RC0603JR-07330RL: as R7 on sheet TIDM_TM4C129USBHS_Micro
R34 = CRCW12061M00JNEA: RES, 1.0 M, 5%, 0.25 W, 1206; Manufacturer: Vishay-Dale; CompType: Resistor; Value: 1.0Meg; Res_ohm: 1000000; Value_Code: 1M00; Tolerance_%: 5; Power_W: 0.25; Value2: 0.25W; VDC_V: 200; TempCo: 200 ppm/C; EIA_Code: E24; U/M: EA; AEC Category: Q200

## Sheet TIDM_TM4C129USBHS_USB.SchDoc
size 431 x 279 mm; Date: Not shown in title block; ApprovedBy: Not shown in title block; CheckedBy: Not shown in title block; Author: Not shown in title block; CompanyName: Not shown in title block; Engineer: Not shown in title block; Organization: Not shown in title block; Address1: Not shown in title block; Address2: Not shown in title block; Address3: Not shown in title block; Address4: Not shown in title block; DocumentNumber: 1; Revision: Use project parameter SCH_Rev; SheetNumber: 4; SheetTotal: 4; PageSetup: Record=PageOptions¦CenterHorizontal=True¦CenterVertical=True¦PrintScale=1.00¦XCorrection=1.00¦YCorrection=1.00¦PrintKind=0¦BorderSize=5000000¦LeftOffset=0¦BottomOffset=0¦Orientation=2¦PaperLength=1000¦PaperWidth=1000¦Scale=100¦PaperSource=15¦PrintQuality=600¦MediaType=1¦DitherType=10¦PaperKind=Letter¦PrintScaleMode=1
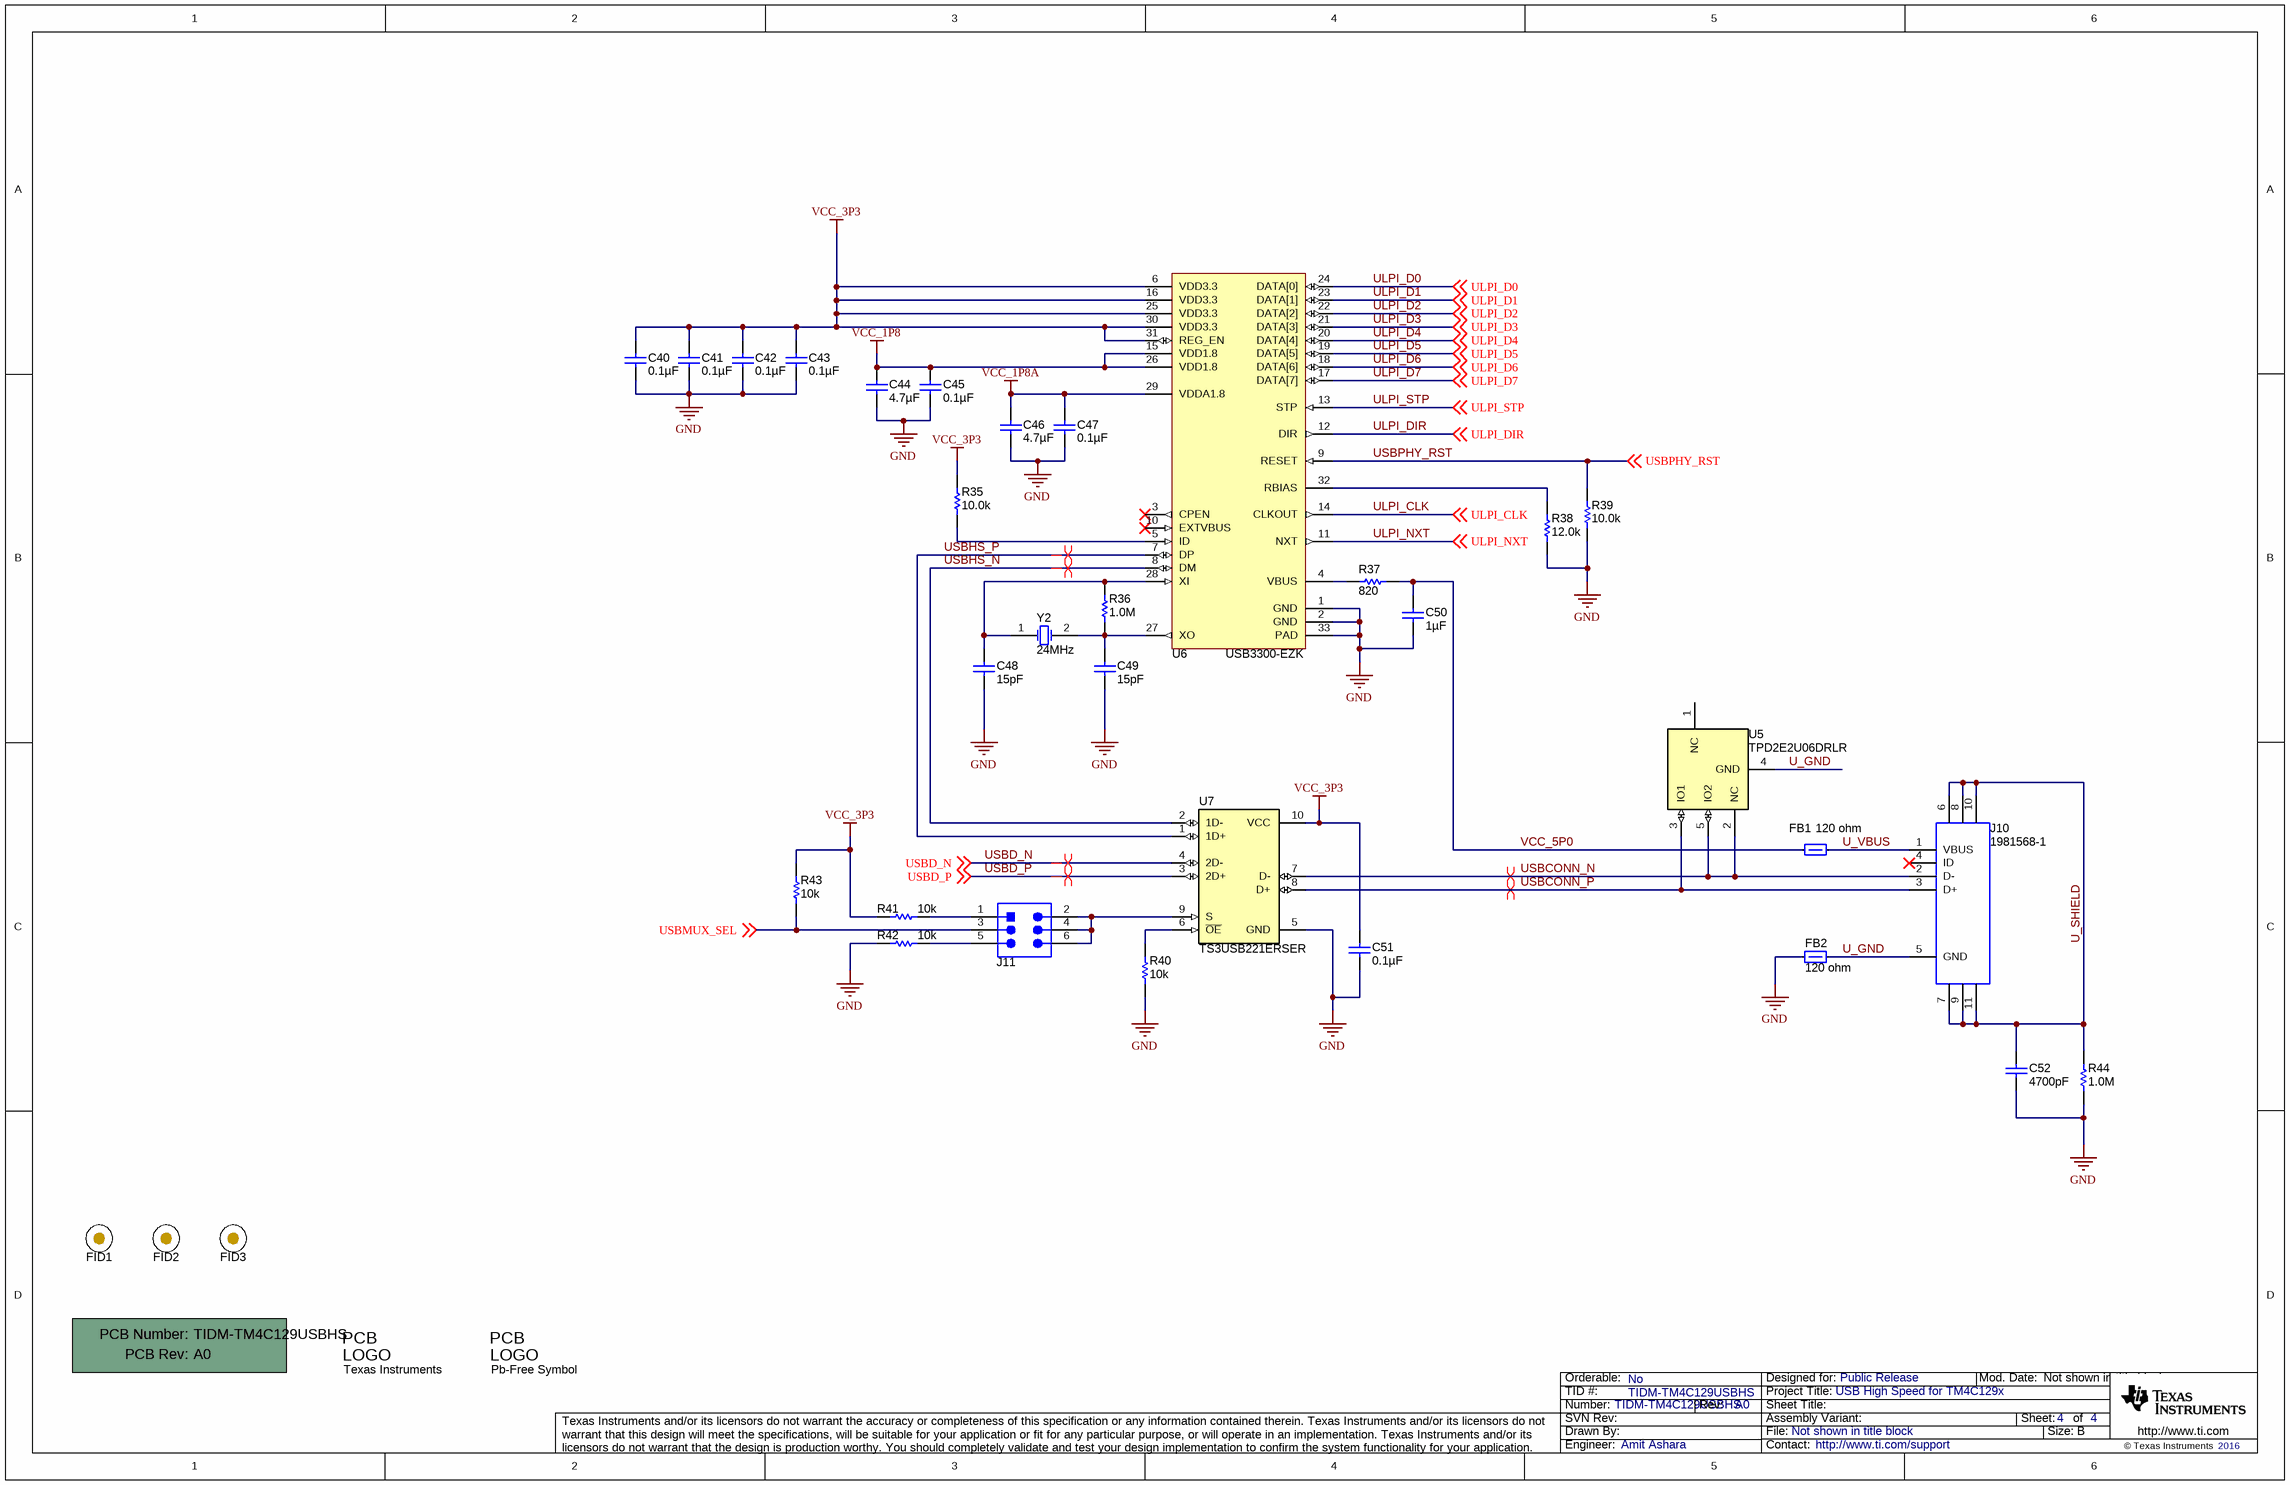
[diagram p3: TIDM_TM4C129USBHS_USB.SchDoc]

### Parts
!PCB  Printed Circuit Board  (value not drawn)  (mechanical)
C40  ValueDisplayed: 0.1µF  [0603]  (hidden comment: 06035C104KAT2A)
C41  ValueDisplayed: 0.1µF  [0603]  (hidden comment: 06035C104KAT2A)
C42  ValueDisplayed: 0.1µF  [0603]  (hidden comment: 06035C104KAT2A)
C43  ValueDisplayed: 0.1µF  [0603]  (hidden comment: 06035C104KAT2A)
C44  ValueDisplayed: 4.7µF  [0805_HV]  (hidden comment: C2012X7R1A475M)
C45  ValueDisplayed: 0.1µF  [0603]  (hidden comment: 06035C104KAT2A)
C46  ValueDisplayed: 4.7µF  [0805_HV]  (hidden comment: C2012X7R1A475M)
C47  ValueDisplayed: 0.1µF  [0603]  (hidden comment: 06035C104KAT2A)
C48  ValueDisplayed: 15pF  [0603]  (hidden comment: 06035A150JAT2A)
C49  ValueDisplayed: 15pF  [0603]  (hidden comment: 06035A150JAT2A)
C50  ValueDisplayed: 1µF  [0603]  (hidden comment: GRM188R71A105KA61D)
C51  ValueDisplayed: 0.1µF  [0603]  (hidden comment: 06035C104KAT2A)
C52  ValueDisplayed: 4700pF  [1812]  (hidden comment: 1812GC472KA1)
FB1  value 120 ohm  [0603]  (hidden comment: BLM18AG121SN1D)
FB2  value 120 ohm  [0603]  (hidden comment: BLM18AG121SN1D)
FID1  Fiducial  [Fiducial10-20]  (value not drawn)
FID2  Fiducial  [Fiducial10-20]  (value not drawn)
FID3  Fiducial  [Fiducial10-20]  (value not drawn)
J10  1981568-1  [TE_1981568-1]
J11  TSW-103-07-G-D  [TSW-103-07-G-D]  (value not drawn)
Logo1  Texas Instruments  [TI_Stacked_Overlay_Small]  (no BOM)
Logo2  Pb-Free Symbol  [Pb-Free_Overlay_Small]  (no BOM)
R35  ValueDisplayed: 10.0k  [0603]  (hidden comment: RCG060310K0FKEA)
R36  ValueDisplayed: 1.0M  [0603]  (hidden comment: CRCW06031M00JNEA)
R37  ValueDisplayed: 820  [0603]  (hidden comment: RC0603FR-07820RL)
R38  ValueDisplayed: 12.0k  [0603]  (hidden comment: RC0603FR-0712KL)
R39  ValueDisplayed: 10.0k  [0603]  (hidden comment: RCG060310K0FKEA)
R40  ValueDisplayed: 10k  [0603]  (hidden comment: RC0603JR-0710KL)
R41  ValueDisplayed: 10k  [0603]  (hidden comment: RC0603JR-0710KL)
R42  ValueDisplayed: 10k  [0603]  (hidden comment: RC0603JR-0710KL)
R43  ValueDisplayed: 10k  [0603]  (hidden comment: RC0603JR-0710KL)
R44  ValueDisplayed: 1.0M  [1206]  (hidden comment: CRCW12061M00JNEA)
U5  TPD2E2U06DRLR  [DRL0005A]
U6  USB3300-EZK  [Microchip_32QFN-3304-5x5B]
U7  TS3USB221ERSER  [RSE0010A]
Y2  Frequency: 24MHz  [NDK_NX5032GA]  (hidden comment: NX5032GA-24.000M-STD-CSK-4)

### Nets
GND: C40.2 C41.2 C42.2 C43.2 C44.2 C45.2 C46.2 C47.2 C48.2 C49.2 C50.2 C51.1 C52.2 FB2.2 R38.1 R39.1 R40.1 R42.2 R44.1 U6.1(GND) U6.2(GND) U6.33(PAD) U7.5(GND)
VCC_1P8: C44.1 C45.1 U6.15(VDD1.8) U6.26(VDD1.8)
VCC_1P8A: C46.1 C47.1 U6.29(VDDA1.8)
VCC_3P3: C40.1 C41.1 C42.1 C43.1 C51.2 R35.2 R41.2 R43.2 U6.6(VDD3.3) U6.16(VDD3.3) U6.25(VDD3.3) U6.30(VDD3.3) U6.31(REG_EN) U7.10(VCC)
VCC_5P0: C50.1 FB1.1 R37.2
U_GND: FB2.1 J10.5(GND) U5.4(GND)
U_SHIELD: C52.1 J10.6 J10.7 J10.8 J10.9 J10.10 J10.11 R44.2
U_VBUS: FB1.2 J10.1(VBUS)
ULPI_CLK: U6.14(CLKOUT) ; off-sheet ULPI_CLK
ULPI_D0: U6.24(DATA[0]) ; off-sheet ULPI_D0
ULPI_D1: U6.23(DATA[1]) ; off-sheet ULPI_D1
ULPI_D2: U6.22(DATA[2]) ; off-sheet ULPI_D2
ULPI_D3: U6.21(DATA[3]) ; off-sheet ULPI_D3
ULPI_D4: U6.20(DATA[4]) ; off-sheet ULPI_D4
ULPI_D5: U6.19(DATA[5]) ; off-sheet ULPI_D5
ULPI_D6: U6.18(DATA[6]) ; off-sheet ULPI_D6
ULPI_D7: U6.17(DATA[7]) ; off-sheet ULPI_D7
ULPI_DIR: U6.12(DIR) ; off-sheet ULPI_DIR
ULPI_NXT: U6.11(NXT) ; off-sheet ULPI_NXT
ULPI_STP: U6.13(STP) ; off-sheet ULPI_STP
USBCONN_N: J10.2(D-) U5.2(NC) U5.5(IO2) U7.7(D-)
USBCONN_P: J10.3(D+) U5.3(IO1) U7.8(D+)
USBD_N: U7.4(2D-) ; off-sheet USBD_N
USBD_P: U7.3(2D+) ; off-sheet USBD_P
USBHS_N: U6.8(DM) U7.2(1D-)
USBHS_P: U6.7(DP) U7.1(1D+)
USBMUX_SEL: J11.3 R43.1 ; off-sheet USBMUX_SEL
USBPHY_RST: R39.2 U6.9(RESET) ; off-sheet USBPHY_RST
NetC48_1: C48.1 R36.2 U6.28(XI) Y2.1(OSC1)
NetC49_1: C49.1 R36.1 U6.27(XO) Y2.2(OSC2)
NetJ11_1: J11.1 R41.1
NetJ11_2: J11.2 J11.4 J11.6 U7.9(S)
NetJ11_5: J11.5 R42.1
NetR35_1: R35.1 U6.5(ID)
NetR37_1: R37.1 U6.4(VBUS)
NetR38_2: R38.2 U6.32(RBIAS)
NetR40_2: R40.2 U7.6(~{OE})

Not connected (* = marked no-connect by the designer): J10 4(ID)*; U5 1(NC); U6 3(CPEN)* 10(EXTVBUS)*

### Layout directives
differential pair: USBCONN_N, USBCONN_P, USBD_N, USBD_P, USBHS_N, USBHS_P

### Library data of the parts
!PCB = PCB: Manufacturer: Any; PartNumber: TIDM-TM4C129USBHS; SymbolCreator: a0412235
C40-C43 C45 C47 C51 = 06035C104KAT2A: CAP, CERM, 0.1 µF, 50 V, +/- 10%, X7R, 0603; Manufacturer: AVX; Polarized: N; CompType: Capacitor; Value: 0.1uF; U/M: EA; Cap_F: 0.0000001; Tolerance_%: 10; Value1: Unknown; VDC_V: 50; Value2: 50V; TaMin_C: -55; TaMax_C: 125; AEC Category: Q200
C44 C46 = C2012X7R1A475M: CAP, CERM, 4.7 µF, 10 V, +/- 20%, X7R, 0805; Manufacturer: TDK; Polarized: N; CompType: Capacitor; Value: 4.7uF; U/M: EA; Cap_F: 0.0000047; Tolerance_%: 20; Value1: Unknown; VDC_V: 10; Value2: 10V; TaMin_C: -55; TaMax_C: 125; Cap_Case: 0805; AEC Category: Q200
C48 C49 = 06035A150JAT2A: CAP, CERM, 15 pF, 50 V, +/- 5%, C0G/NP0, 0603; Manufacturer: AVX; Polarized: N; CompType: Capacitor; Value: 15pF; U/M: EA; Cap_F: 0.000000000015; Tolerance_%: 5; ESR_ohm: 0.32; Value1: 0.32 ohm; VDC_V: 50; Value2: 50V; TaMin_C: -55; TaMax_C: 125; AEC Category: Q200
C50 = GRM188R71A105KA61D: CAP, CERM, 1 µF, 10 V, +/- 10%, X7R, 0603; Manufacturer: MuRata; Polarized: N; CompType: Capacitor; Value: 1uF; U/M: EA; Cap_F: 0.000001; Tolerance_%: 10; ESR_ohm: 0.011; Value1: 0.011 ohm; Value2: 10V; TaMin_C: -55; TaMax_C: 125; AEC Category: Q200
C52 = 1812GC472KA1: as C39 on sheet TIDM_TM4C129USBHS_Ethernet
FB1 FB2 = BLM18AG121SN1D: Ferrite Bead, 120 ohm @ 100 MHz, 0.5 A, 0603; Manufacturer: MuRata; Imax_A: 0.5; DCR_ohm: 0.18; Value1: 0.18 ohm; Value2: 0.5A; ZTyp@100MHz_Ohm: 120
FID1-FID3 = Fiducial: Fiducial mark.  There is nothing to buy or mount.; SymbolCreator: codlsc
J10 = 1981568-1: Connector, Receptacle, Micro-USB Type B, R/A, Bottom Mount SMT; Manufacturer: TE Connectivity; SymbolCreator: a0411947
J11 = TSW-103-07-G-D: Header, 100mil, 3x2, Gold, TH; Manufacturer: Samtec; SymbolCreator: a0412235; Pitch_mm: 2.54; Gender: Male; Shrouded: N; Row_Count: 2; Current_A: 6.3; Voltage_V: 550; Cert_CSA: Y
Logo1 = TI_Logo: Texas Instrument Corporate Signature; SymbolCreator: codlsc
Logo2 = Pb-Free: SymbolCreator: a0412235
R35 R39 = RCG060310K0FKEA: RES, 10.0 k, 1%, 0.1 W, 0603; Manufacturer: Vishay Draloric; CompType: Resistor; Value: 10.0k; Res_ohm: 10000; Value_Code: 10k0; Tolerance_%: 1; Power_W: 0.1; Value2: 0.1W; VDC_V: 75; TempCo: 100 ppm/C; EIA_Code: E96; U/M: EA; AEC Category: Q200; AEC Qualified: N
R36 = CRCW06031M00JNEA: as R20 on sheet TIDM_TM4C129USBHS_Connector
R37 = RC0603FR-07820RL: RES, 820, 1%, 0.1 W, 0603; Manufacturer: Yageo America; CompType: Resistor; Value: 820; Value_Code: 820R; Tolerance_%: 1; Power_W: 0.1; Value2: 0.1W; VDC_V: 150; TempCo: 200 ppm/C; U/M: EA; AEC Category: Q200
R38 = RC0603FR-0712KL: RES, 12.0 k, 1%, 0.1 W, 0603; Manufacturer: Yageo America; CompType: Resistor; Value: 12.0k; Res_ohm: 12000; Value_Code: 12k0; Tolerance_%: 1; Power_W: 0.1; Value2: 0.1W; VDC_V: 150; TempCo: 200 ppm/C; U/M: EA; AEC Category: Q200
R40-R43 = RC0603JR-0710KL: RES, 10 k, 5%, 0.1 W, 0603; Manufacturer: Yageo America; CompType: Resistor; Value: 10k; Res_ohm: 10000; Value_Code: 10k0; Tolerance_%: 5; Power_W: 0.1; Value2: 0.1W; VDC_V: 50; TempCo: 100 ppm/C; EIA_Code: E24; U/M: EA; AEC Category: Q200
R44 = CRCW12061M00JNEA: as R34 on sheet TIDM_TM4C129USBHS_Ethernet
U5 = TPD2E2U06DRLR: DUAL CHANNEL HIGH SPEED ESD PROTECTION DEVICE, DRL0005A; Manufacturer: Texas Instruments; SymbolCreator: a0411947; CompType: IC; U/M: EA
U6 = USB3300-EZK: Hi-Speed USB Host, Device or OTG PHY with ULPI Low Pin Interface, QFN-32; Manufacturer: Microchip; SymbolCreator: a0411947
U7 = TS3USB221ERSER: High-Speed USB 2.0 (480 Mbps) 1:2 Multiplexer / Demultiplexer Switch with Single Enable, 6 ohm RON, 2.5 to 3.3V, -40 to 85 degC, 10-Pin UQFN (RSE), Green (RoHS & no Sb/Br); Manufacturer: Texas Instruments; Alternate PartNumber: Equivalent; SubFamily: USB Switch; Number of Channels: 2; Architecture: 1; ESD HBM(kV): +/-7; OFF Time(Max)(ns): 30; Vcc range(V): 2.3 to 3.6; tpd max(ns): 0.25; ron(max)(ohms): 6; RON Mis-match(Max)(Ohms): 0.2; Bandwidth(MHz): 1200; ON Time(Max)(ns): 5
Y2 = NX5032GA-24.000M-STD-CSK-4: Crystal, 24MHz,  SMD; Manufacturer: NDK; SymbolCreator: a0412235; U/M: EA; TaMin_C: -40; TaMax_C: 150; Frequency Stability: ±30ppm

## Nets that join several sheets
GND: TIDM_TM4C129USBHS_Micro (42 pins), TIDM_TM4C129USBHS_Connector (45 pins), TIDM_TM4C129USBHS_Ethernet (9 pins), TIDM_TM4C129USBHS_USB (23 pins)
VCC_3P3: TIDM_TM4C129USBHS_Micro (34 pins), TIDM_TM4C129USBHS_Connector (12 pins), TIDM_TM4C129USBHS_Ethernet (10 pins), TIDM_TM4C129USBHS_USB (14 pins)
VCC_5P0: TIDM_TM4C129USBHS_Micro (C23.1 R6.1 U2.1), TIDM_TM4C129USBHS_Connector (C26.1 U3.3), TIDM_TM4C129USBHS_USB (C50.1 FB1.1 R37.2)
AIN0: TIDM_TM4C129USBHS_Micro (U1.12), TIDM_TM4C129USBHS_Connector (J2.16)
AIN1: TIDM_TM4C129USBHS_Micro (U1.13), TIDM_TM4C129USBHS_Connector (J2.15)
AIN2: TIDM_TM4C129USBHS_Micro (U1.14), TIDM_TM4C129USBHS_Connector (J2.18)
AIN3: TIDM_TM4C129USBHS_Micro (U1.15), TIDM_TM4C129USBHS_Connector (J2.17)
CAN1RX: TIDM_TM4C129USBHS_Micro (U1.95), TIDM_TM4C129USBHS_Connector (U3.4)
CAN1TX: TIDM_TM4C129USBHS_Micro (U1.96), TIDM_TM4C129USBHS_Connector (U3.1)
ENETLED0: TIDM_TM4C129USBHS_Micro (U1.63), TIDM_TM4C129USBHS_Ethernet (J9.12)
ENETLED1: TIDM_TM4C129USBHS_Micro (U1.61), TIDM_TM4C129USBHS_Ethernet (J9.9)
EPHYRX_N: TIDM_TM4C129USBHS_Micro (U1.53), TIDM_TM4C129USBHS_Ethernet (D4.1 D4.8 J9.6 R31.1)
EPHYRX_P: TIDM_TM4C129USBHS_Micro (U1.54), TIDM_TM4C129USBHS_Ethernet (D4.2 D4.7 J9.3 R30.1)
EPHYTX_N: TIDM_TM4C129USBHS_Micro (U1.56), TIDM_TM4C129USBHS_Ethernet (D4.3 D4.6 J9.2 R29.1)
EPHYTX_P: TIDM_TM4C129USBHS_Micro (U1.57), TIDM_TM4C129USBHS_Ethernet (D4.4 D4.5 J9.1 R28.1)
GPIOLED1: TIDM_TM4C129USBHS_Micro (U1.31), TIDM_TM4C129USBHS_Connector (D2.1)
GPIOLED2: TIDM_TM4C129USBHS_Micro (U1.32), TIDM_TM4C129USBHS_Connector (D3.1)
GPIOSW1: TIDM_TM4C129USBHS_Micro (U1.22), TIDM_TM4C129USBHS_Connector (C28.1 R23.1 R24.1)
GPIOSW2: TIDM_TM4C129USBHS_Micro (U1.23), TIDM_TM4C129USBHS_Connector (C29.1 R25.1 R26.1)
I2C1SCL: TIDM_TM4C129USBHS_Micro (U1.49), TIDM_TM4C129USBHS_Connector (J2.13 R9.1)
I2C1SDA: TIDM_TM4C129USBHS_Micro (U1.50), TIDM_TM4C129USBHS_Connector (J2.11 R8.1)
JTAG_TCK: TIDM_TM4C129USBHS_Micro (U1.100), TIDM_TM4C129USBHS_Connector (R12.2 R16.1)
JTAG_TDI: TIDM_TM4C129USBHS_Micro (U1.98), TIDM_TM4C129USBHS_Connector (R14.2)
JTAG_TDO: TIDM_TM4C129USBHS_Micro (U1.97), TIDM_TM4C129USBHS_Connector (R13.2 R17.2)
JTAG_TMS: TIDM_TM4C129USBHS_Micro (U1.99), TIDM_TM4C129USBHS_Connector (R11.2 R15.1)
MCU_GPIO0: TIDM_TM4C129USBHS_Micro (U1.1), TIDM_TM4C129USBHS_Connector (U8.16)
MCU_GPIO1: TIDM_TM4C129USBHS_Micro (U1.2), TIDM_TM4C129USBHS_Connector (U8.14)
MCU_GPIO2: TIDM_TM4C129USBHS_Micro (U1.3), TIDM_TM4C129USBHS_Connector (U8.13)
MCU_GPIO3: TIDM_TM4C129USBHS_Micro (U1.4), TIDM_TM4C129USBHS_Connector (U8.12)
MCU_GPIO4: TIDM_TM4C129USBHS_Micro (U1.107), TIDM_TM4C129USBHS_Connector (U8.11)
MCU_GPIO5: TIDM_TM4C129USBHS_Micro (U1.108), TIDM_TM4C129USBHS_Connector (U8.10)
RST_N: TIDM_TM4C129USBHS_Micro (C22.1 R4.1 R5.1 U1.70), TIDM_TM4C129USBHS_Connector (J3.10 J4.10)
SSI3CLK: TIDM_TM4C129USBHS_Micro (U1.5), TIDM_TM4C129USBHS_Connector (J2.2)
SSI3FSS: TIDM_TM4C129USBHS_Micro (U1.6), TIDM_TM4C129USBHS_Connector (J2.4)
SSI3XDAT0: TIDM_TM4C129USBHS_Micro (U1.11), TIDM_TM4C129USBHS_Connector (J2.6)
SSI3XDAT1: TIDM_TM4C129USBHS_Micro (U1.27), TIDM_TM4C129USBHS_Connector (J2.8)
SSI3XDAT2: TIDM_TM4C129USBHS_Micro (U1.118), TIDM_TM4C129USBHS_Connector (J2.9)
SSI3XDAT3: TIDM_TM4C129USBHS_Micro (U1.119), TIDM_TM4C129USBHS_Connector (J2.7)
TRCLK: TIDM_TM4C129USBHS_Micro (U1.45), TIDM_TM4C129USBHS_Connector (J4.12)
TRD0: TIDM_TM4C129USBHS_Micro (U1.44), TIDM_TM4C129USBHS_Connector (J4.14)
TRD1: TIDM_TM4C129USBHS_Micro (U1.43), TIDM_TM4C129USBHS_Connector (J4.16)
TRD2: TIDM_TM4C129USBHS_Micro (U1.42), TIDM_TM4C129USBHS_Connector (J4.18)
TRD3: TIDM_TM4C129USBHS_Micro (U1.46), TIDM_TM4C129USBHS_Connector (J4.20)
U0CTS: TIDM_TM4C129USBHS_Micro (U1.30), TIDM_TM4C129USBHS_Connector (U4.9)
U0RTS: TIDM_TM4C129USBHS_Micro (U1.29), TIDM_TM4C129USBHS_Connector (U4.11)
U0RX: TIDM_TM4C129USBHS_Micro (U1.33), TIDM_TM4C129USBHS_Connector (U4.12)
U0TX: TIDM_TM4C129USBHS_Micro (U1.34), TIDM_TM4C129USBHS_Connector (U4.10)
U2RX: TIDM_TM4C129USBHS_Micro (U1.125), TIDM_TM4C129USBHS_Connector (J2.5)
U2TX: TIDM_TM4C129USBHS_Micro (U1.126), TIDM_TM4C129USBHS_Connector (J2.3)
ULPI_CLK: TIDM_TM4C129USBHS_Micro (U1.92), TIDM_TM4C129USBHS_USB (U6.14)
ULPI_D0: TIDM_TM4C129USBHS_Micro (U1.81), TIDM_TM4C129USBHS_USB (U6.24)
ULPI_D1: TIDM_TM4C129USBHS_Micro (U1.82), TIDM_TM4C129USBHS_USB (U6.23)
ULPI_D2: TIDM_TM4C129USBHS_Micro (U1.83), TIDM_TM4C129USBHS_USB (U6.22)
ULPI_D3: TIDM_TM4C129USBHS_Micro (U1.84), TIDM_TM4C129USBHS_USB (U6.21)
ULPI_D4: TIDM_TM4C129USBHS_Micro (U1.85), TIDM_TM4C129USBHS_USB (U6.20)
ULPI_D5: TIDM_TM4C129USBHS_Micro (U1.86), TIDM_TM4C129USBHS_USB (U6.19)
ULPI_D6: TIDM_TM4C129USBHS_Micro (U1.106), TIDM_TM4C129USBHS_USB (U6.18)
ULPI_D7: TIDM_TM4C129USBHS_Micro (U1.105), TIDM_TM4C129USBHS_USB (U6.17)
ULPI_DIR: TIDM_TM4C129USBHS_Micro (U1.104), TIDM_TM4C129USBHS_USB (U6.12)
ULPI_NXT: TIDM_TM4C129USBHS_Micro (U1.103), TIDM_TM4C129USBHS_USB (U6.11)
ULPI_STP: TIDM_TM4C129USBHS_Micro (U1.91), TIDM_TM4C129USBHS_USB (U6.13)
USBD_N: TIDM_TM4C129USBHS_Micro (U1.93), TIDM_TM4C129USBHS_USB (U7.4)
USBD_P: TIDM_TM4C129USBHS_Micro (U1.94), TIDM_TM4C129USBHS_USB (U7.3)
USBMUX_SEL: TIDM_TM4C129USBHS_Micro (U1.128), TIDM_TM4C129USBHS_USB (J11.3 R43.1)
USBPHY_RST: TIDM_TM4C129USBHS_Micro (U1.124), TIDM_TM4C129USBHS_USB (R39.2 U6.9)

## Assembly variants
001: not fitted FID1 FID2 FID3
